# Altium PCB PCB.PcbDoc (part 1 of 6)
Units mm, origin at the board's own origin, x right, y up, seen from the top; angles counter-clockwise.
Board outline 101.6 x 101.61 mm, 4 copper layers (Top Layer, GND, POWER, Bottom Layer), stack 1.371 mm thick; 506 components, 346 nets, 1798 pads, 1471 vias.
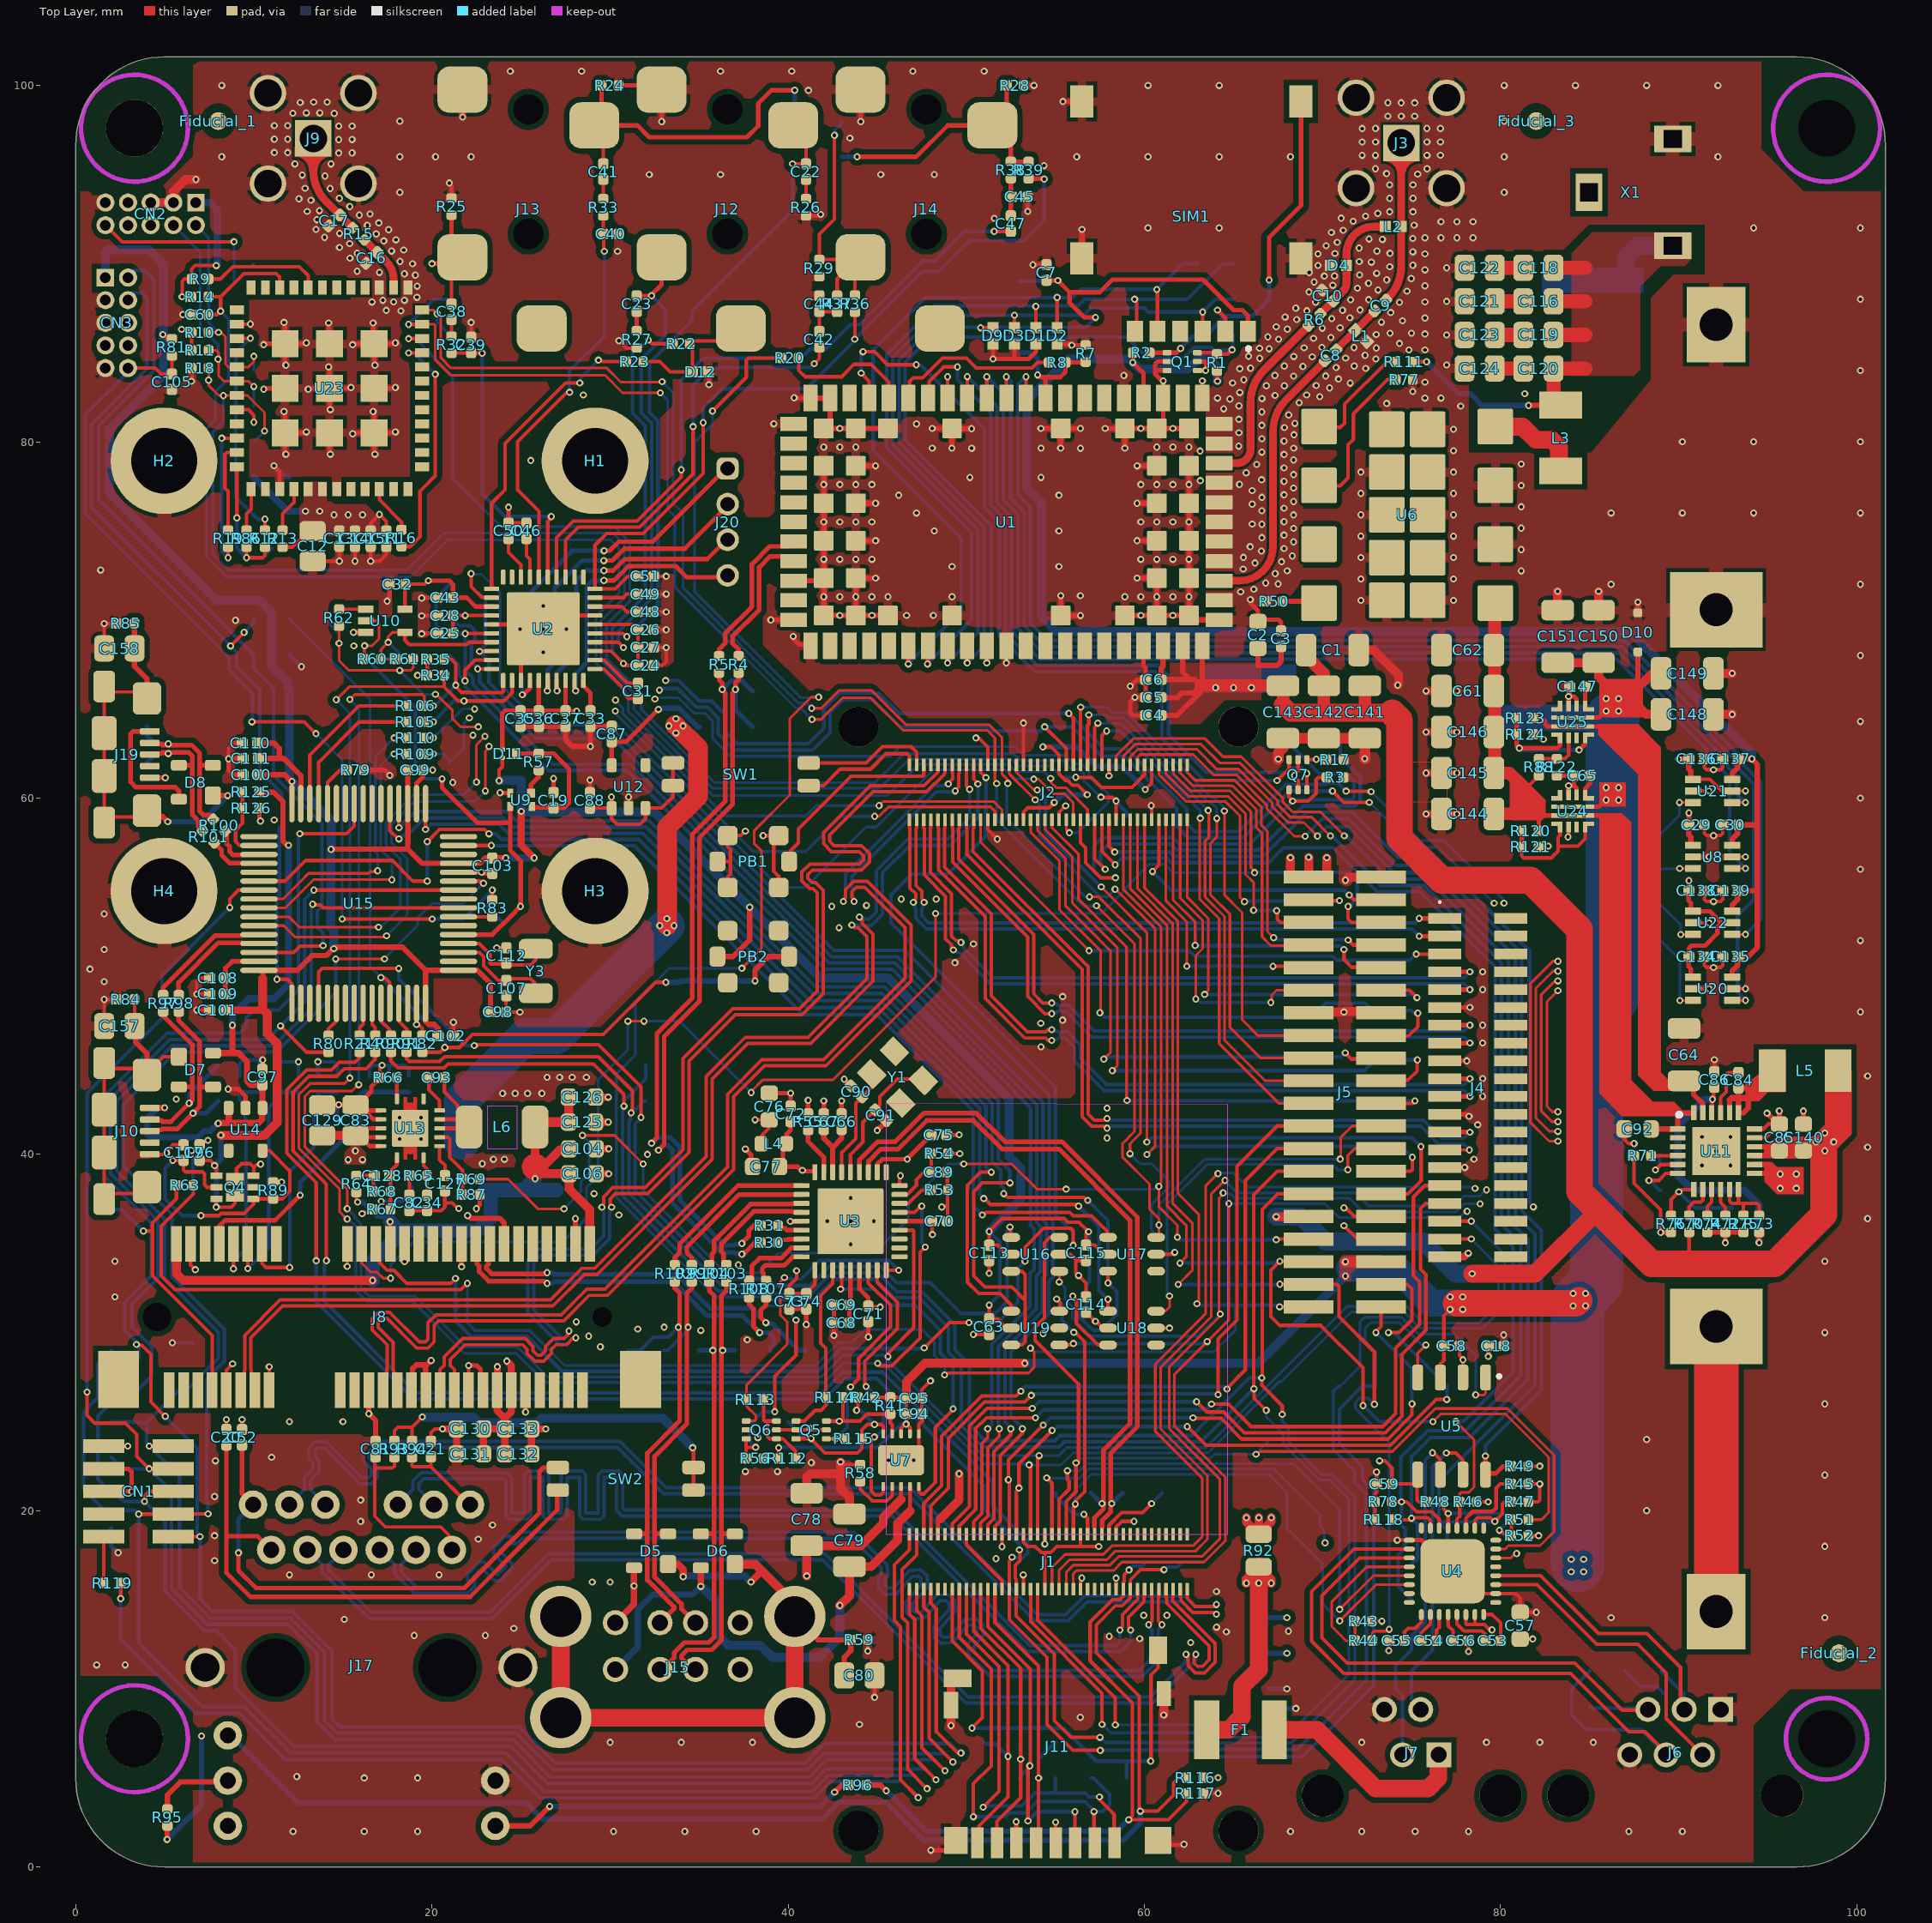
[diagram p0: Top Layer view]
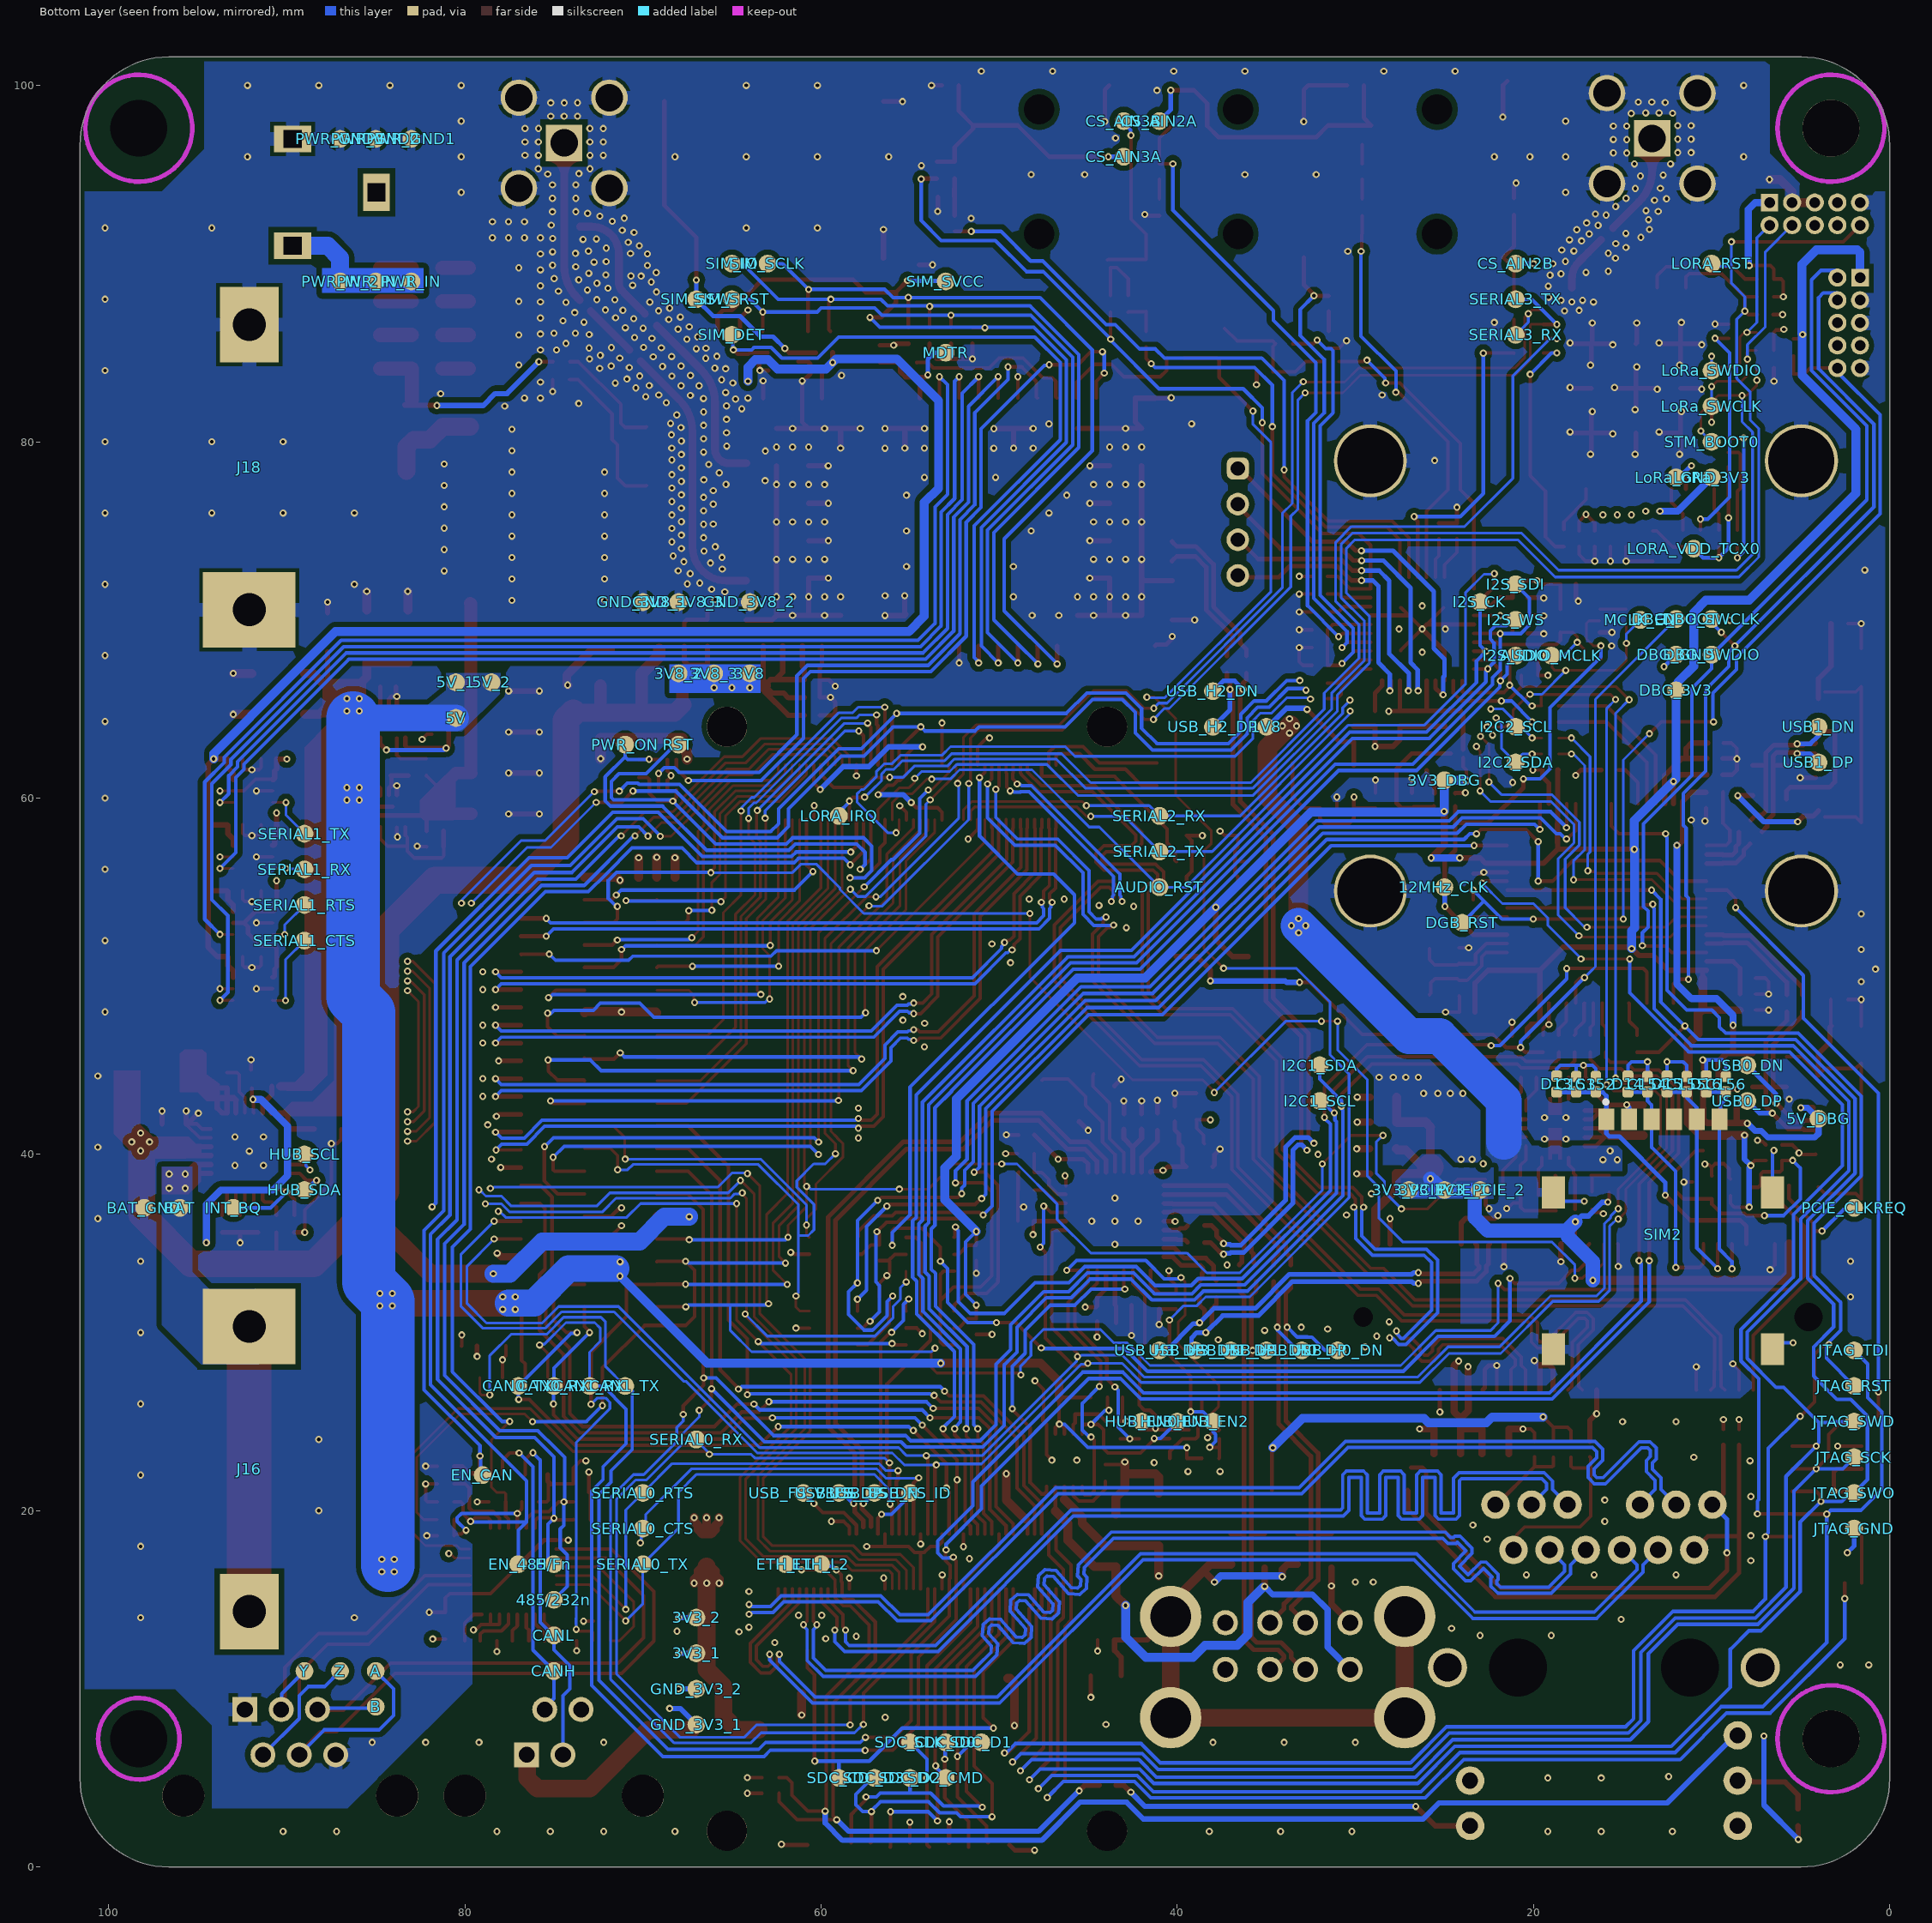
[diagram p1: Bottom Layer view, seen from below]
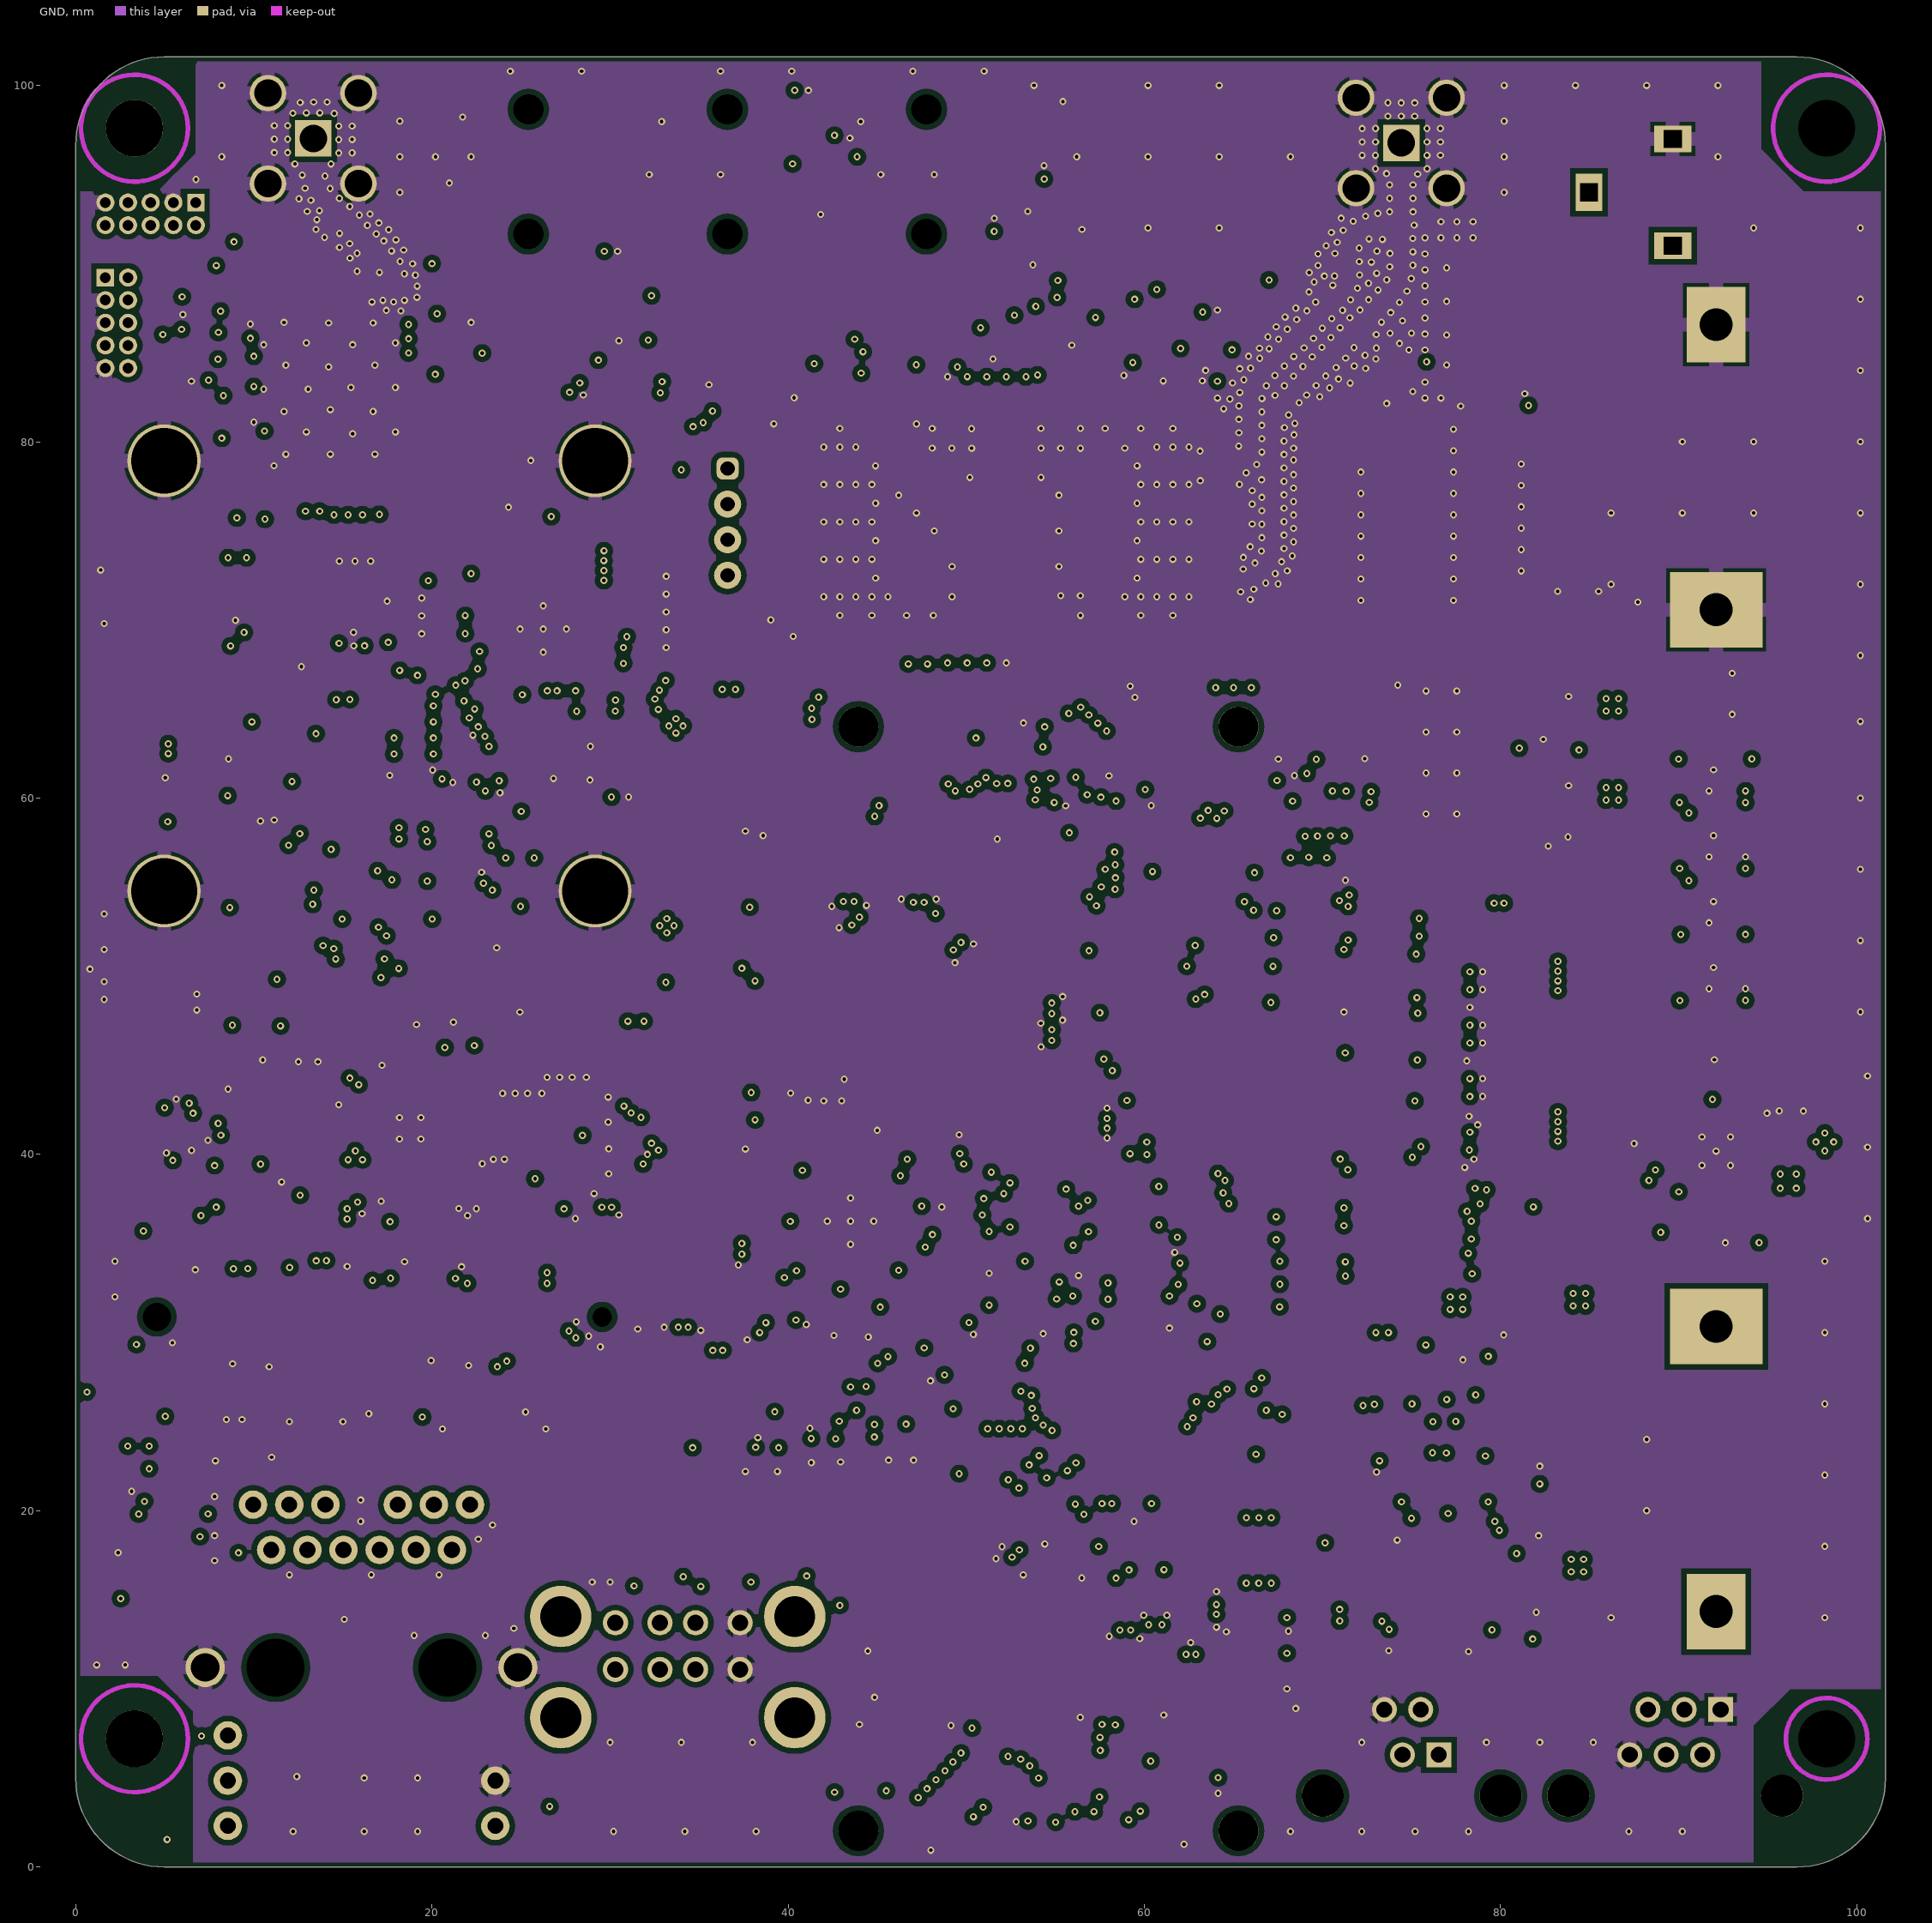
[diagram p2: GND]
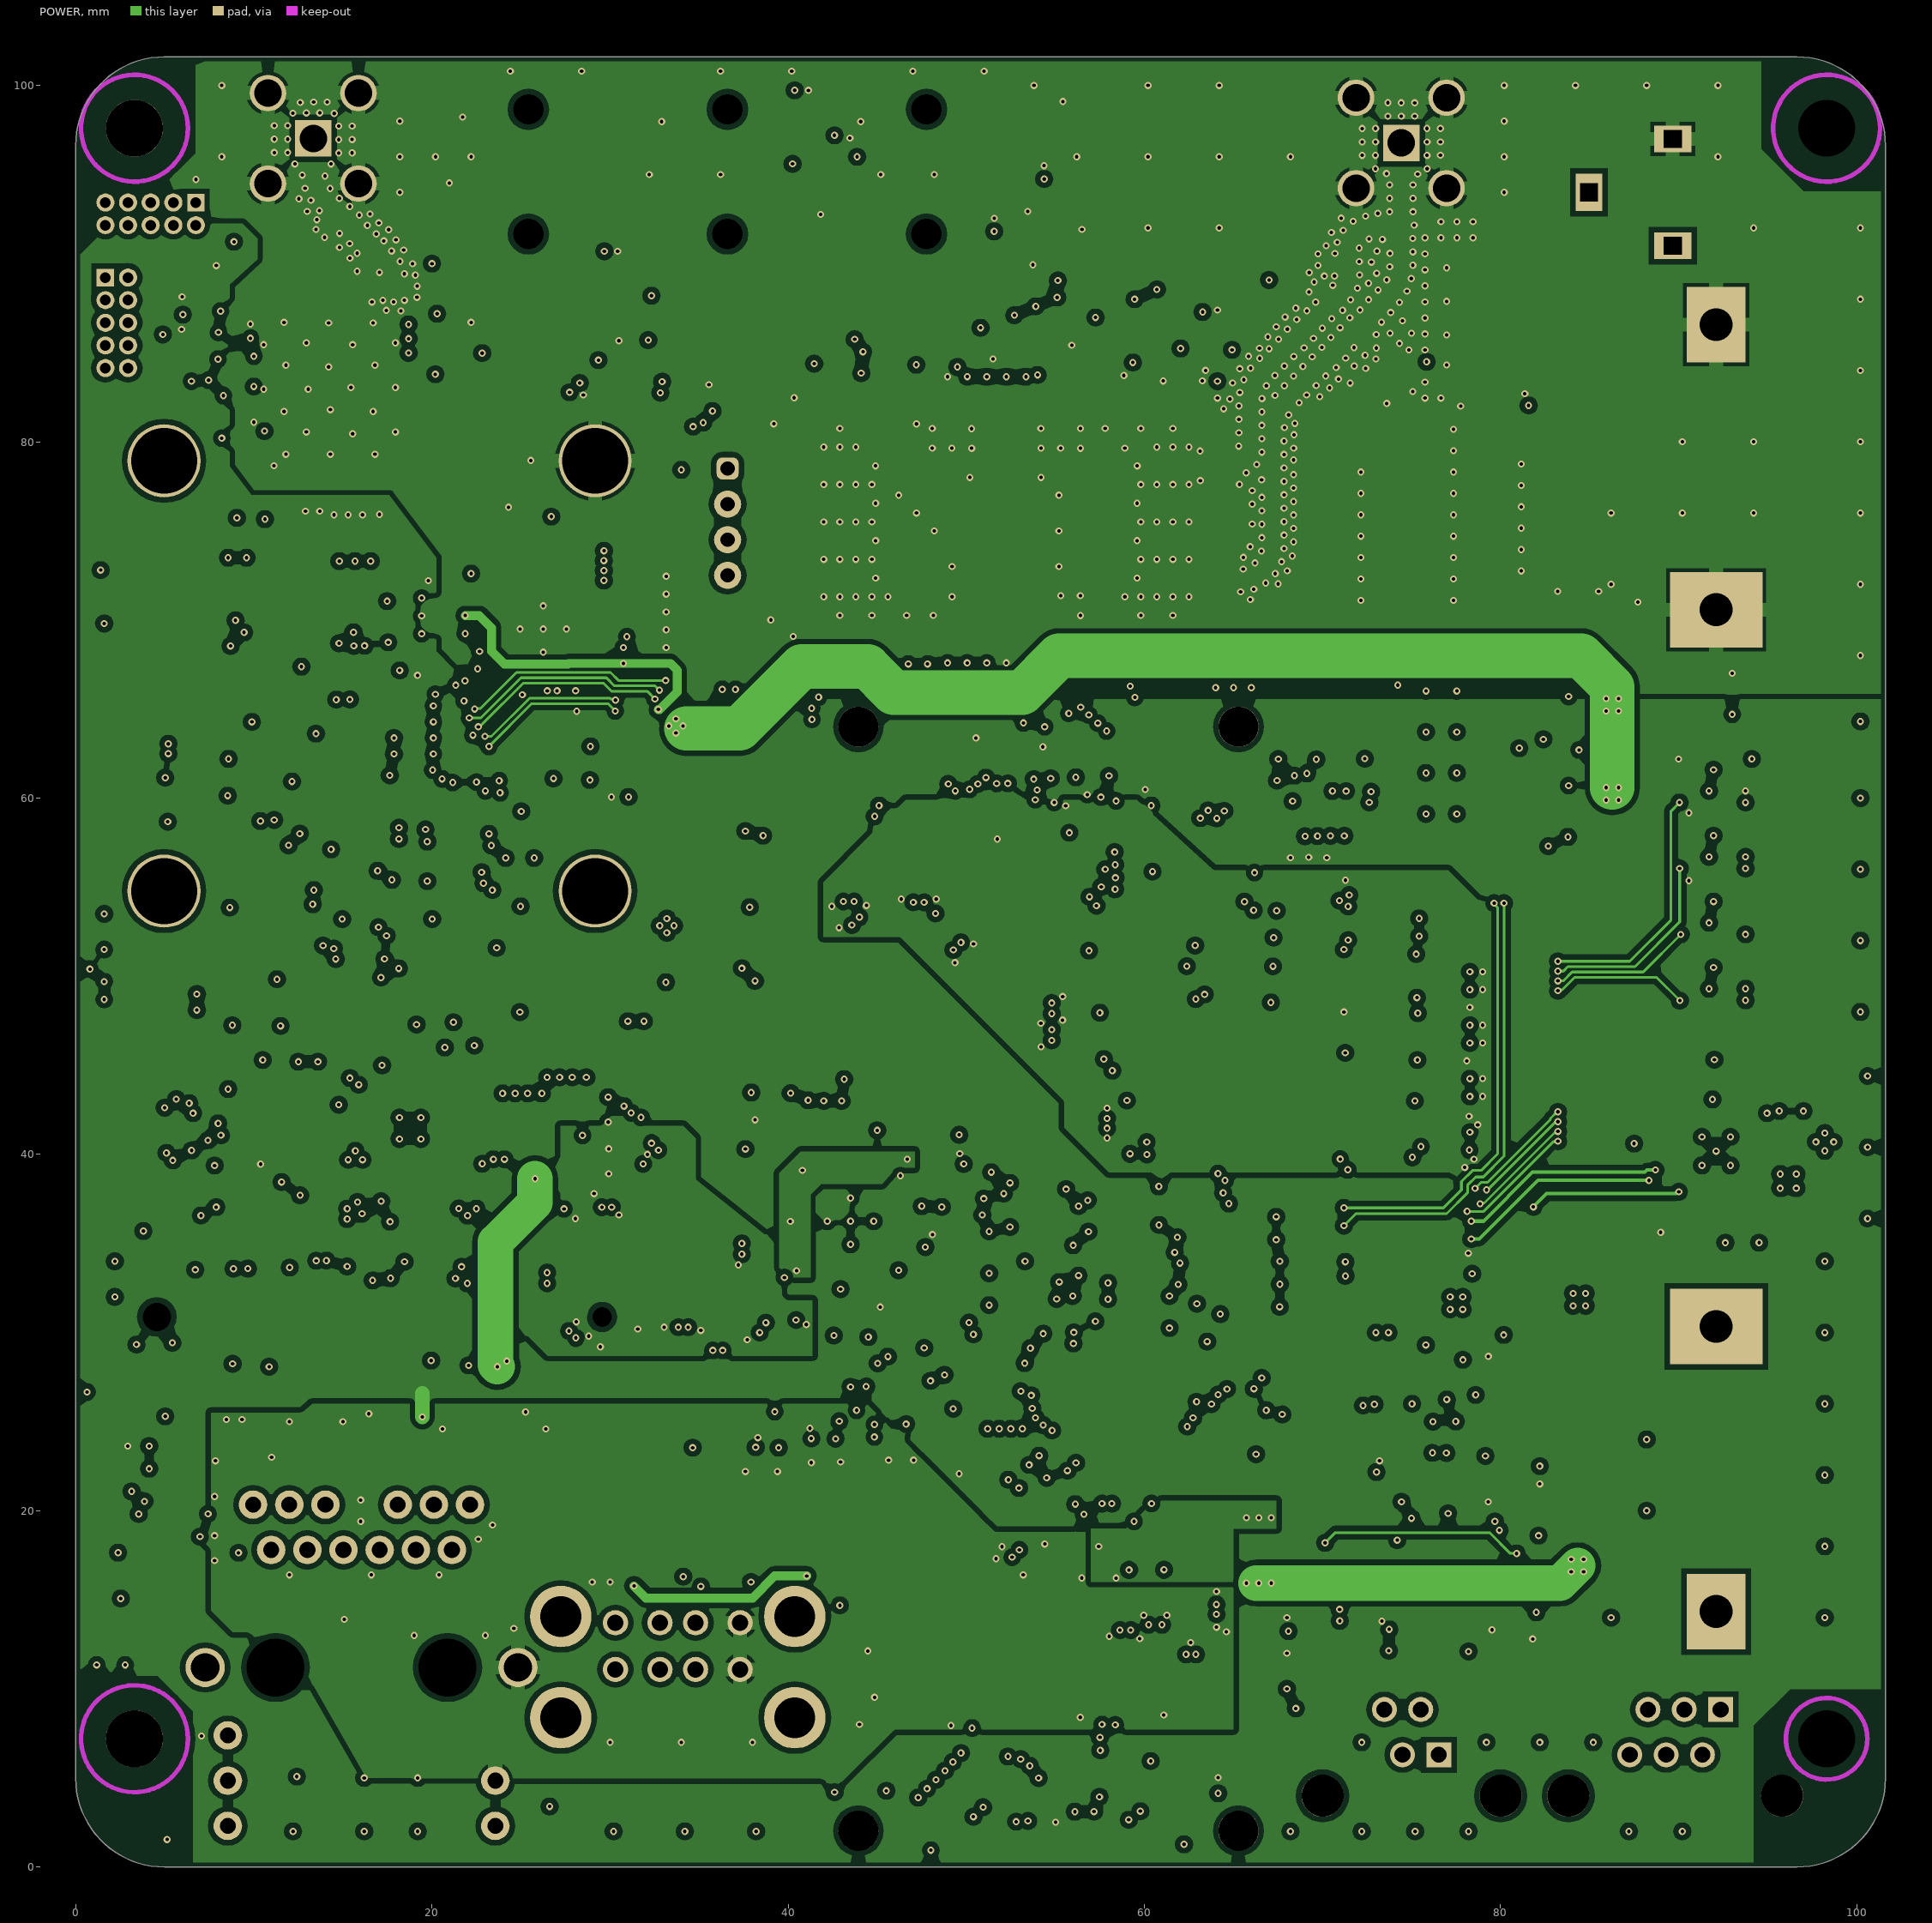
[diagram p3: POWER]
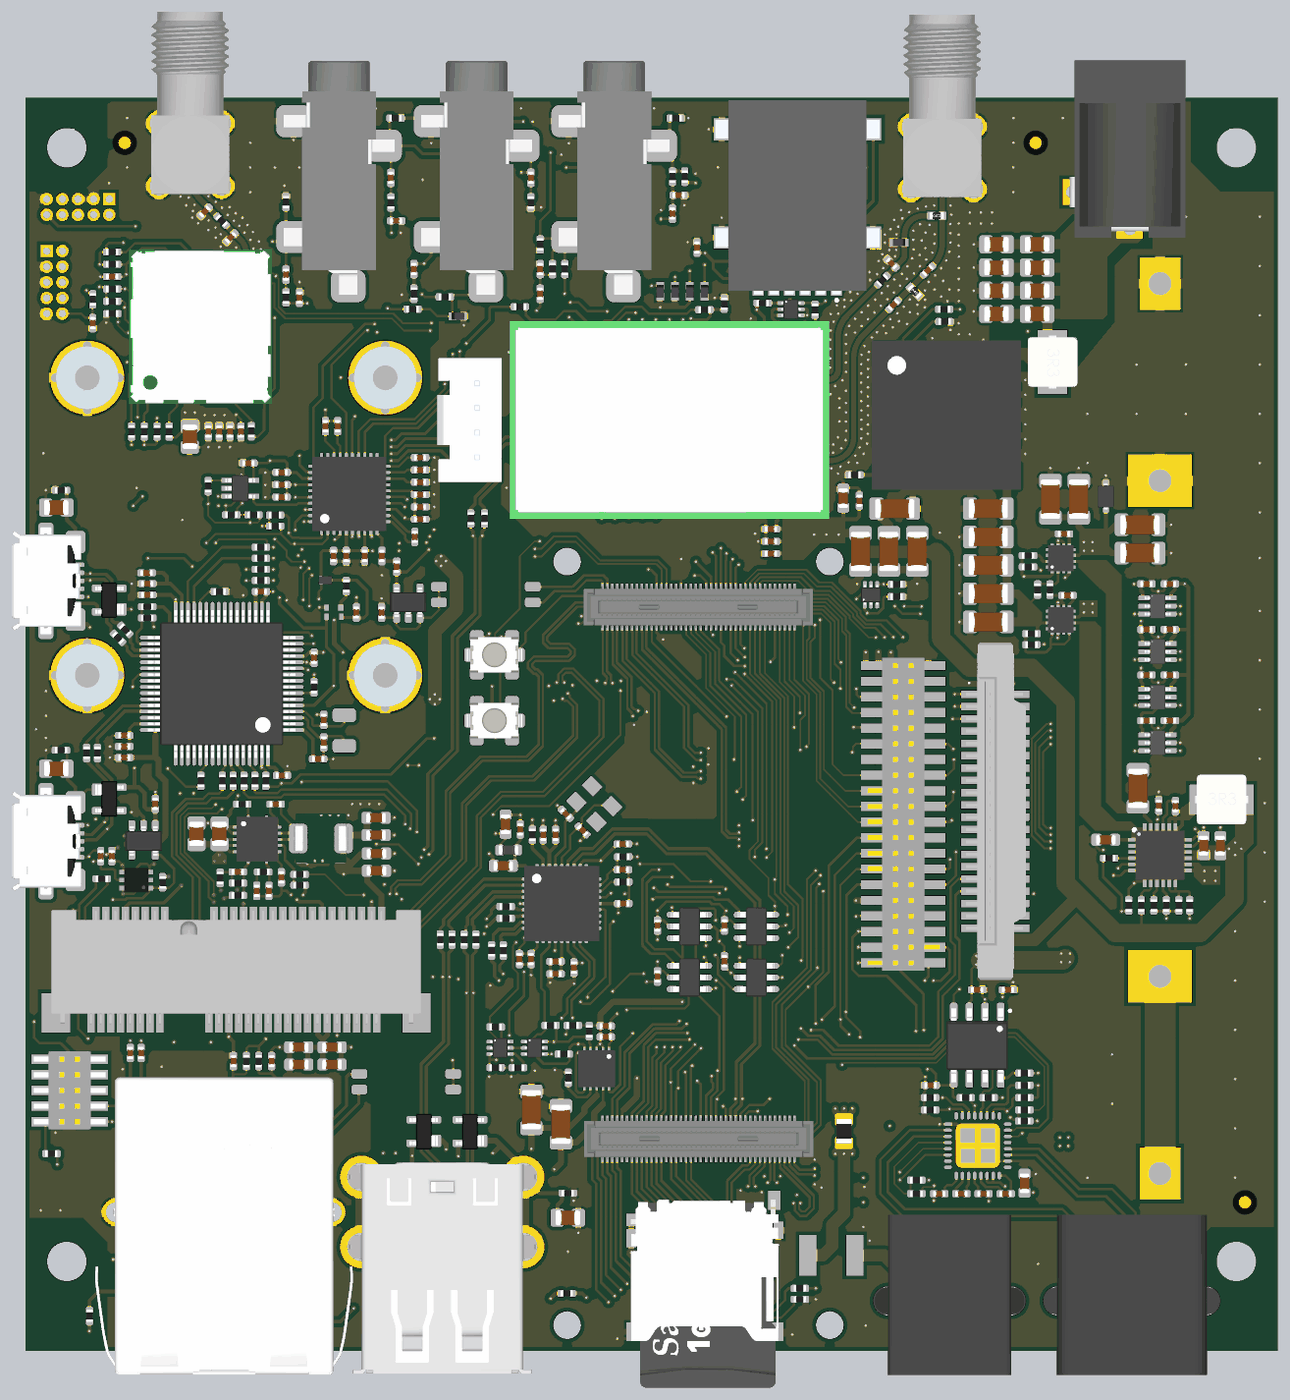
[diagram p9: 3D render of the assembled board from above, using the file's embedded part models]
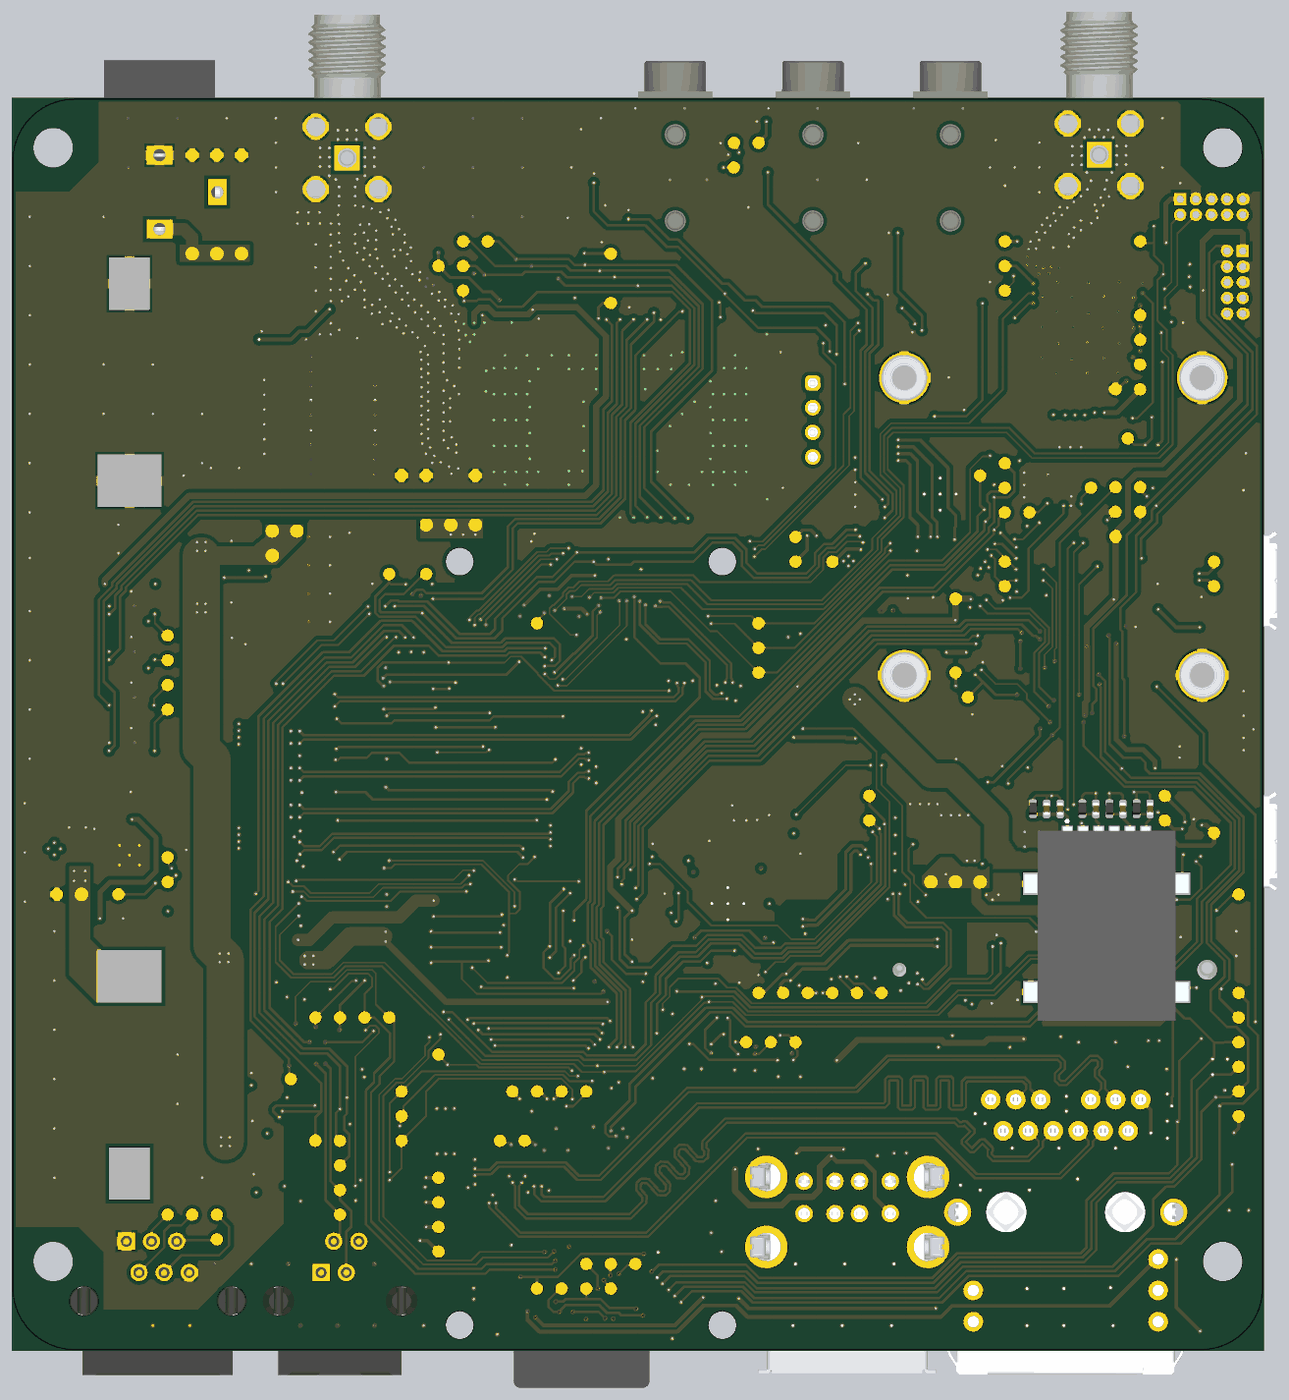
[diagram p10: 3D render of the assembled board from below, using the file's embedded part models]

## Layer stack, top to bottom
Top Solder: solder mask 0.025, SM-001, Dk 4
Top Layer: signal copper 0.035
Dielectric 1: prepreg 0.13, PP-017, Dk 4.3
Dielectric 2: prepreg 0.13, PP-017, Dk 4.3
GND: signal copper 0.035
Dielectric 3: core 0.711, Core-039, Dk 4.8
POWER: signal copper 0.035
Dielectric 4: prepreg 0.13, PP-017, Dk 4.3
Dielectric 5: prepreg 0.13, PP-017, Dk 4.3
Bottom Layer: signal copper 0.035
Bottom Solder: solder mask 0.025, SM-001, Dk 4

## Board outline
0,4.978 0.001,4.979 0.001,96.628 cw(c4.978,96.628) 4.978,101.606 4.978,101.605 96.627,101.605 cw(c96.627,96.627) 101.605,96.627 101.605,4.978 cw(c96.627,4.978) 96.627,0.001 4.978,0.001 cw(c4.978,4.978)

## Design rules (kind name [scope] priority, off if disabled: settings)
BoardOutlineClearance mousebits [(ObjectKind = 'Pad') And (Component = 'Free') And (Name = 'Free-T2') And (AsMM(HoleDiameter) = 0.5)] p1: gap=0 ignorepadtopadclearanceinfootprint=FALSE
BoardOutlineClearance [All] p2: gap=0.25 ignorepadtopadclearanceinfootprint=FALSE
Clearance RF_COPLANAR [InNamedPolygon('RF_COPLANAR')] p1: gap=0.15 ignorepadtopadclearanceinfootprint=FALSE
Clearance PWR3_3V3 [InNamedPolygon('+3V3A_L03_P069')] p2: gap=0.3 ignorepadtopadclearanceinfootprint=TRUE
Clearance Clearance_PWR [InPolygon] p3: gap=0.3 ignorepadtopadclearanceinfootprint=TRUE
Clearance Clearance_lay2 [All vs OnLayer('Layer 2')] p4: gap=0.3 ignorepadtopadclearanceinfootprint=TRUE
Clearance Clearance_gnd [InNet('GND')] p5: gap=0.15 ignorepadtopadclearanceinfootprint=TRUE
Clearance [All] p6: gap=0.15 ignorepadtopadclearanceinfootprint=TRUE
ComponentClearance TP_to_TP [HasFootprint('TP-1.00MM') vs HasFootprint('TP-1.00MM')] p1: gap=0.85 collisioncheckmode=3 verticalgap=-10 showdistances=FALSE
ComponentClearance BATTERY [All vs (ObjectKind = 'Component') And (Comment = '254TR')] p2: gap=-100 collisioncheckmode=3 verticalgap=2540 showdistances=FALSE
ComponentClearance STANDOFF [All vs (ObjectKind = 'Component') And (Footprint = 'STM-LQFP64_M')] p3: gap=0 collisioncheckmode=3 verticalgap=2540 showdistances=FALSE
ComponentClearance [All] p4: gap=0.254 collisioncheckmode=3 verticalgap=0.254 showdistances=FALSE
DiffPairsRouting [InDifferentialPairClass('PCIE')] p1: maxlimit=0.254 minlimit=0.15 mostfreqgap=0.254 toplayer_maxgap=0.15 toplayer_prefgap=0.15 toplayer_minwidth=0.26 toplayer_maxwidth=0.26 toplayer_prefwidth=0.26 bottomlayer_maxgap=0.15 bottomlayer_prefgap=0.15 bottomlayer_minwidth=0.26 bottomlayer_maxwidth=0.26 bottomlayer_prefwidth=0.26 impedanceprofiledriven=TRUE impedanceprofileid={86AA89F2-88DE-4668-8F6C-DF2D7110B5BD} impedanceprofilevalue=90.000000 maxuncoupledlength=12.7
DiffPairsRouting DiffPairsRouting_USB [InDifferentialPairClass('USB')] p2: maxlimit=0.254 minlimit=0.15 mostfreqgap=0.254 toplayer_maxgap=0.15 toplayer_prefgap=0.15 toplayer_minwidth=0.26 toplayer_maxwidth=0.26 toplayer_prefwidth=0.26 bottomlayer_maxgap=0.15 bottomlayer_prefgap=0.15 bottomlayer_minwidth=0.26 bottomlayer_maxwidth=0.26 bottomlayer_prefwidth=0.26 impedanceprofiledriven=TRUE impedanceprofileid={86AA89F2-88DE-4668-8F6C-DF2D7110B5BD} impedanceprofilevalue=90.000000 maxuncoupledlength=12.7
DiffPairsRouting DiffPairsRouting_ETH [InDifferentialPairClass('ETH')] p3: maxlimit=0.254 minlimit=0.15 mostfreqgap=0.254 toplayer_maxgap=0.15 toplayer_prefgap=0.15 toplayer_minwidth=0.19 toplayer_maxwidth=0.19 toplayer_prefwidth=0.19 bottomlayer_maxgap=0.15 bottomlayer_prefgap=0.15 bottomlayer_minwidth=0.19 bottomlayer_maxwidth=0.19 bottomlayer_prefwidth=0.19 impedanceprofiledriven=TRUE impedanceprofileid={794067FB-18C5-4D87-800B-9EEDAD137A72} impedanceprofilevalue=100.000000 maxuncoupledlength=12.7
DiffPairsRouting DiffPairsRouting_DSI [InDifferentialPairClass('DSI')] p4: maxlimit=0.254 minlimit=0.15 mostfreqgap=0.254 toplayer_maxgap=0.15 toplayer_prefgap=0.15 toplayer_minwidth=0.19 toplayer_maxwidth=0.19 toplayer_prefwidth=0.19 bottomlayer_maxgap=0.15 bottomlayer_prefgap=0.15 bottomlayer_minwidth=0.19 bottomlayer_maxwidth=0.19 bottomlayer_prefwidth=0.19 impedanceprofiledriven=TRUE impedanceprofileid={794067FB-18C5-4D87-800B-9EEDAD137A72} impedanceprofilevalue=100.000000 maxuncoupledlength=12.7
DiffPairsRouting DiffPairsRouting_CAMERA [InDifferentialPairClass('CAMERA')] p5: maxlimit=0.254 minlimit=0.15 mostfreqgap=0.254 toplayer_maxgap=0.15 toplayer_prefgap=0.15 toplayer_minwidth=0.19 toplayer_maxwidth=0.19 toplayer_prefwidth=0.19 bottomlayer_maxgap=0.15 bottomlayer_prefgap=0.15 bottomlayer_minwidth=0.19 bottomlayer_maxwidth=0.19 bottomlayer_prefwidth=0.19 impedanceprofiledriven=TRUE impedanceprofileid={794067FB-18C5-4D87-800B-9EEDAD137A72} impedanceprofilevalue=100.000000 maxuncoupledlength=12.7
HoleSize [All] p1 off: absolutevalues=TRUE maxlimit=2.54 minlimit=0.025 maxpercent=80.000 minpercent=20.000
MatchedLengths match_PCIE [InDifferentialPairClass('PCIE')] p1: tolerance=1.5 checknetsindiffpair=TRUE checkdiffpairvsdiffpair=FALSE checkxsignals=FALSE checkothers=FALSE
MatchedLengths MatchedLengths_eth [InDifferentialPairClass('ETH')] p2: tolerance=1.5 checknetsindiffpair=TRUE checkdiffpairvsdiffpair=FALSE checkxsignals=FALSE checkothers=FALSE
MatchedLengths MatchedLengths_dsi [InDifferentialPairClass('DSI')] p3: tolerance=1.5 checknetsindiffpair=TRUE checkdiffpairvsdiffpair=FALSE checkxsignals=FALSE checkothers=FALSE
MatchedLengths [InAnyDifferentialPair] p4: tolerance=1.5 checknetsindiffpair=TRUE checkdiffpairvsdiffpair=FALSE checkxsignals=FALSE checkothers=FALSE
PlaneConnect [All] p1: pad.planeconnectstyle=Relief pad.reliefexpansion=0.3 pad.reliefentries=4 pad.reliefconductorwidth=0.5 pad.reliefairgap=0.2 via.planeconnectstyle=Direct via.reliefexpansion=0.508 via.reliefentries=4 via.reliefconductorwidth=0.254 via.reliefairgap=0.254
PolygonConnect PWR_IN [All vs InNamedPolygon('PRW_IN')] p1: thpad.connectstyle=Direct thpad.reliefconductorwidth=0.254 thpad.reliefentries=4 thpad.polygonreliefangle="90 Angle" thpad.airgapwidth=0.254 smdpad.connectstyle=Relief smdpad.reliefconductorwidth=0.4 smdpad.reliefentries=4 smdpad.polygonreliefangle="90 Angle" smdpad.airgapwidth=0.4 via.connectstyle=Direct via.reliefconductorwidth=0.254 via.reliefentries=4 via.polygonreliefangle="90 Angle" via.airgapwidth=0.254
PolygonConnect No_reliefs [IsNamedPolygon('No_reliefs')] p2: connectstyle=Direct reliefconductorwidth=0.254 reliefentries=4 polygonreliefangle="90 Angle" airgapwidth=0.254
PolygonConnect RF_COPLANAR_1 [All vs IsNamedPolygon('RF_COPLANAR')] p3: thpad.connectstyle=Relief thpad.reliefconductorwidth=0.254 thpad.reliefentries=4 thpad.polygonreliefangle="90 Angle" thpad.airgapwidth=0.254 smdpad.connectstyle=Direct smdpad.reliefconductorwidth=0.254 smdpad.reliefentries=4 smdpad.polygonreliefangle="90 Angle" smdpad.airgapwidth=0.254 via.connectstyle=Direct via.reliefconductorwidth=0.254 via.reliefentries=4 via.polygonreliefangle="90 Angle" via.airgapwidth=0.254
PolygonConnect GND_only [InNet('GND')] p4: thpad.connectstyle=Relief thpad.reliefconductorwidth=0.8 thpad.reliefentries=4 thpad.polygonreliefangle="90 Angle" thpad.airgapwidth=0.2 smdpad.connectstyle=Relief smdpad.reliefconductorwidth=0.5 smdpad.reliefentries=4 smdpad.polygonreliefangle="90 Angle" smdpad.airgapwidth=0.2 via.connectstyle=Direct via.reliefconductorwidth=0.254 via.reliefentries=4 via.polygonreliefangle="90 Angle" via.airgapwidth=0.254
PolygonConnect Signal_only [All] p5: connectstyle=Direct reliefconductorwidth=0.254 reliefentries=4 polygonreliefangle="90 Angle" airgapwidth=0.254
RoomDefinition PORTENTA [InComponentClass('PORTENTA')] p1: confinementstyle=ConfineIn formatcopy=TRUE lockcomponents=FALSE outline 0,0 50.8,0 50.8,25.4 0,25.4
RoomDefinition ETH_CONNECTOR [InComponentClass('ETH_CONNECTOR')] p2: confinementstyle=ConfineIn formatcopy=TRUE lockcomponents=FALSE outline 0,0 50.8,0 50.8,25.4 0,25.4
RoomDefinition DBG [InComponentClass('DBG')] p3 off: confinementstyle=ConfineIn formatcopy=TRUE lockcomponents=FALSE outline 102.743,1.397 330.937,1.397 330.937,18.567 102.743,18.567
RoomDefinition "USB Host" [InComponentClass('USB Host')] p4 off: confinementstyle=ConfineIn formatcopy=TRUE lockcomponents=FALSE outline 0,0 50.8,0 50.8,25.4 0,25.4
RoomDefinition TOP [InComponentClass('TOP')] p5 off: confinementstyle=ConfineIn formatcopy=TRUE lockcomponents=FALSE outline 0,0 50.8,0 50.8,25.4 0,25.4
RoomDefinition SD [InComponentClass('SD')] p6 off: confinementstyle=ConfineIn formatcopy=TRUE lockcomponents=FALSE outline 102.743,5.055 107.086,5.055 107.086,9.728 102.743,9.728
RoomDefinition "RS485 and CAN" [InComponentClass('RS485 and CAN')] p7 off: confinementstyle=ConfineIn formatcopy=TRUE lockcomponents=FALSE outline 0,0 50.8,0 50.8,25.4 0,25.4
RoomDefinition "Power supply" [InComponentClass('Power supply')] p8 off: confinementstyle=ConfineIn formatcopy=TRUE lockcomponents=FALSE outline 0,0 50.8,0 50.8,25.4 0,25.4
RoomDefinition PCIE [InComponentClass('PCIE')] p9 off: confinementstyle=ConfineIn formatcopy=TRUE lockcomponents=FALSE outline 0,0 50.8,0 50.8,25.4 0,25.4
RoomDefinition "Lora Module" [InComponentClass('Lora Module')] p10 off: confinementstyle=ConfineIn formatcopy=TRUE lockcomponents=FALSE outline 0,0 50.8,0 50.8,25.4 0,25.4
RoomDefinition HUB [InComponentClass('HUB')] p11 off: confinementstyle=ConfineIn formatcopy=TRUE lockcomponents=FALSE outline 0,0 50.8,0 50.8,25.4 0,25.4
RoomDefinition "Cellular Module" [InComponentClass('Cellular Module')] p12 off: confinementstyle=ConfineIn formatcopy=TRUE lockcomponents=FALSE outline 102.743,1.397 106.07,1.397 106.07,5.156 102.743,5.156
RoomDefinition Camera [InComponentClass('Camera')] p13 off: confinementstyle=ConfineIn formatcopy=TRUE lockcomponents=FALSE outline 0,0 50.8,0 50.8,25.4 0,25.4
RoomDefinition Audio [InComponentClass('Audio')] p14 off: confinementstyle=ConfineIn formatcopy=TRUE lockcomponents=FALSE outline 0,0 50.8,0 50.8,25.4 0,25.4
RoutingVias [All] p1: holewidth=0.2 width=0.4 viastyle="Through Hole" minholewidth=0.2 minwidth=0.4 maxholewidth=0.2 maxwidth=0.4
SolderMaskExpansion [IsVia] p1: expansion=0.102 istentingtop=TRUE
SolderMaskExpansion SolderMaskExpansion_1 [All] p2: expansion=0.05 istentingtop=FALSE
ViasUnderSMD [All] p1: allowed=FALSE
Width 50R [InNet('NetC17_2') OR InNet('NetC16_2')  OR InNet('NetC8_1') OR InNet('NetR6_1')] p1: maxlimit=0.447 minlimit=0.274 preferedwidth=0.447 toplayer_minwidth=0.44 midlayer1_maxwidth=0.284 midlayer1_prefwidth=0.284 midlayer2_maxwidth=0.284 midlayer2_prefwidth=0.284 bottomlayer_minwidth=0.44 impedanceprofiledriven=TRUE impedanceprofileid={5C83D50C-043A-4C5B-A4AB-3CBF0BAC11ED} impedanceprofilevalue=50.000000 minimp=50.000000 maximp=50.000000 favimp=50.000000
Width [All] p2: maxlimit=5 minlimit=0.15 preferedwidth=0.2
26 further rules are at their usual default settings.

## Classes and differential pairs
differential pair class CAMERA: CAMERA.CK_1 CAMERA.D0_1 CAMERA.D1_1 CAMERA.D2_1 CAMERA.D3_1
differential pair class DSI: CAMERA.CK_CK_1 CAMERA.D0_D0_1 CAMERA.D1_D0_1 CAMERA.D2_D1_1 CAMERA.D3_D1_1 CAMERA.D4_D2_1 CAMERA.D5_D2_1 CAMERA.D6_D3_1 CAMERA.VS_CK_1 PCIe.CK_1 PCIe.RX_1 PCIe.TX_1
differential pair class PCIE: PCIe.CK_1 PCIe.RX_1 PCIe.TX_1
differential pair class ETH: ETH.A_1 ETH.B_1 ETH.C_1 ETH.D_1
component class DBG: C63 C98 C99 C100 C101 C102 C103 C105 C107 C108 C109 C110 C111 C112 C113 C114 C115 C157 C158 CN3 D7 D8 DBG_3V3 DBG_BOOT DBG_GND DBG_SWCLK DBG_SWDIO DGB_RST J10 J19 PB2 R21 R40 R79 R80 R81 R82 R83 R84 R85 R90 R91 R97 R98 R100 R101 R105 R106 R109 R110 R125 R126 U15 U16 U17 U18 U19 USB0_DN USB0_DP USB1_DN USB1_DP Y3
polygon class GND-BOT: +3V8_L01_P032
differential pair class USB: U0_D U1_D USB0_8 USB0_D_3 USB0_D_RES_3 USB1_8 USB1_D_3 USB1_D_uC_3 USB2_8 USB3_8 USB_FS.D_1 USB_H0.D_1 USB_H1.D_1 USB_H2.D_1 USB_H3.D_1 USB_R_5
component class TOP: 3V3_1 3V3_2 12MHz_CLK AUDIO_MCLK C19 C32 CAN0_RX CAN0_TX CAN1_RX CAN1_TX D11 Fiducial_1 Fiducial_2 Fiducial_3 GND_3V3_1 GND_3V3_2 HUB_SCL HUB_SDA I2C1_SCL I2C1_SDA I2C2_SCL I2C2_SDA I2S_CK I2S_SDI I2S_SDO I2S_WS J5 JTAG_GND JTAG_RST JTAG_SCK JTAG_SWD JTAG_SWO JTAG_TDI MCLK_EN PB1 R57 R60 R61 R62 R92 SERIAL0_CTS SERIAL0_RTS SERIAL0_RX SERIAL0_TX SERIAL1_CTS SERIAL1_RTS SERIAL1_RX SERIAL1_TX SERIAL2_RX SERIAL2_TX SERIAL3_RX SERIAL3_TX SW1 U9 U10 USB_FS_DN USB_FS_DP USB_FS_ID USB_FS_VBUS USB_H0_DN USB_H0_DP USB_H1_DN USB_H1_DP USB_H2_DN USB_H2_DP USB_H3_DN USB_H3_DP
component class "USB Host": C78 C79 C80 C94 C95 D5 D6 J15 R58 R59 U7
component class SD: J11 SDC_CD SDC_CLK SDC_CMD SDC_D0 SDC_D1 SDC_D2 SDC_D3
component class "RS485 and CAN": 485/232n A B C53 C54 C55 C56 C57 C58 C59 CANH CANL EN_485 EN_CAN F1 H/Fn J6 J7 R43 R44 R45 R46 R47 R48 R49 R51 R52 R78 R118 U4 U5 Y Z
component class "Power supply": 1V8 3V3_DBG 3V3_PCIE 3V3_PCIE_1 3V3_PCIE_2 3V8 3V8_2 3V8_3 5V 5V_1 5V_2 5V_DBG BAT BAT_GND C34 C61 C62 C64 C65 C82 C83 C84 C85 C86 C87 C88 C92 C93 C96 C97 C104 C106 C116 C117 C118 C119 C120 C121 C122 C123 C124 C125 C126 C127 C128 C129 C140 C144 C145 C146 C147 C148 C149 C150 C151 D10 GND_3V8_1 GND_3V8_2 GND_3V8_3 INT_BQ J16 J18 L3 L5 L6 PWR_GND1 PWR_GND2 PWR_GND3 PWR_IN PWR_IN_1 PWR_IN_2 Q4 R50 R64 R65 R66 R67 R68 R69 R70 R71 R72 R73 R74 R75 R76 R77 R87 R88 R89 R111 R120 R121 R122 R123 R124 U6 U11 U12 U13 U14 U24 U25 X1
component class PCIE: C130 C131 C132 C133 C152 C153 C154 C155 C156 D13 D14 D15 D16 H1 H2 H3 H4 J8 PCIE_CLKREQ R63 SIM2
component class HUB: C66 C67 C68 C69 C70 C71 C72 C73 C74 C75 C76 C77 C89 C90 C91 HUB_EN0 HUB_EN1 HUB_EN2 L4 Q5 Q6 R30 R31 R41 R42 R53 R54 R55 R56 R99 R102 R103 R104 R107 R108 R112 R113 R114 R115 U3 Y1
component class ETH_CONNECTOR: C20 C21 C52 C81 ETH_L1 ETH_L2 J17 R93 R94 R95 R96 R116 R117 SW2
component class "Cellular Module": C1 C2 C3 C4 C5 C6 C7 C8 C9 C10 C29 C30 C134 C135 C136 C137 C138 C139 C141 C142 C143 D1 D2 D3 D4 D9 J3 L1 L2 MDTR PWR_ON Q1 Q7 R1 R2 R3 R4 R5 R6 R7 R8 R17 R20 RST SIM1 SIM_DET SIM_IO SIM_SCLK SIM_SRST SIM_SSW SIM_SVCC U1 U8 U20 U21 U22
component class Camera: C18 J4
component class Audio: AUDIO_RST C22 C23 C24 C25 C26 C27 C28 C31 C33 C35 C36 C37 C38 C39 C40 C41 C42 C43 C44 C45 C46 C47 C48 C49 C50 C51 CS_AIN2A CS_AIN2B CS_AIN3A CS_AIN3B D12 J12 J13 J14 J20 R22 R23 R24 R25 R26 R27 R28 R29 R32 R33 R34 R35 R36 R37 R38 R39 U2
component class "Lora Module": C11 C12 C13 C14 C15 C16 C17 C60 CN2 J9 LoRa_3V3 LoRa_GND LORA_IRQ LORA_RST LoRa_SWCLK LoRa_SWDIO LORA_VDD_TCX0 R9 R10 R11 R12 R13 R14 R15 R16 R18 R19 R86 STM_BOOT0 U23
component class PORTENTA: CN1 J1 J2 R119
differential pair USB0_D_RES_3: +USB0_D_RES_3_P -USB0_D_RES_3_N
differential pair USB0_D_3: +USB0_D_3_P -USB0_D_3_N
differential pair USB2_8: +USB2_8_P -USB2_8_N
differential pair USB_R_5: +USB_R_5_P -USB_R_5_N
differential pair USB3_8: +USB3_8_P -USB3_8_N
differential pair USB1_D_uC_3: +USB1_D_uC_3_P -USB1_D_uC_3_N
differential pair USB1_D_3: +USB1_D_3_P -USB1_D_3_N
differential pair USB1_8: +USB1_8_P -USB1_8_N
differential pair USB0_8: +USB0_8_P -USB0_8_N
differential pair CAMERA.D3_1: +CAMERA.D3_1_P -CAMERA.D3_1_N
differential pair CAMERA.D2_1: +CAMERA.D2_1_P -CAMERA.D2_1_N
differential pair CAMERA.D1_1: +CAMERA.D1_1_P -CAMERA.D1_1_N
differential pair CAMERA.D0_1: +CAMERA.D0_1_P -CAMERA.D0_1_N
differential pair CAMERA.CK_1: +CAMERA.CK_1_P -CAMERA.CK_1_N
differential pair USB_H3.D_1: +USB_H3.D_1_P -USB_H3.D_1_N
differential pair USB_H2.D_1: +USB_H2.D_1_P -USB_H2.D_1_N
differential pair USB_H1.D_1: +USB_H1.D_1_P -USB_H1.D_1_N
differential pair USB_H0.D_1: +USB_H0.D_1_P -USB_H0.D_1_N
differential pair USB_FS.D_1: +USB_FS.D_1_P -USB_FS.D_1_N
differential pair PCIe.TX_1: +PCIe.TX_1_P -PCIe.TX_1_N
differential pair PCIe.RX_1: +PCIe.RX_1_P -PCIe.RX_1_N
differential pair PCIe.CK_1: +PCIe.CK_1_P -PCIe.CK_1_N
differential pair ETH.D_1: +ETH.D_1_P -ETH.D_1_N
differential pair ETH.C_1: +ETH.C_1_P -ETH.C_1_N
differential pair ETH.B_1: +ETH.B_1_P -ETH.B_1_N
differential pair ETH.A_1: +ETH.A_1_P -ETH.A_1_N

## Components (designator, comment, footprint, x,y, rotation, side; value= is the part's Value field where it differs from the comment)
1V8 "CMP-018-0005-A.3" TP-1.00MM#1 35,64 r90 bottom
3V3_1 "CMP-018-0005-A.3" TP-1.00MM#1 67,12 r180 bottom
3V3_2 "CMP-018-0005-A.3" TP-1.00MM#1 67,14 r180 bottom
3V3_DBG "CMP-018-0005-A.3" TP-1.00MM#1 25,61 r180 bottom
3V3_PCIE "CMP-018-0005-A.3" TP-1.00MM#1 27,38 r90 bottom
3V3_PCIE_1 "CMP-018-0005-A.3" TP-1.00MM#1 25,38 r90 bottom
3V3_PCIE_2 "CMP-018-0005-A.3" TP-1.00MM#1 23,38 r90 bottom
3V8 "CMP-018-0005-A.3" TP-1.00MM#1 64,67 r180 bottom
3V8_2 "CMP-018-0005-A.3" TP-1.00MM#1 68,67 r180 bottom
3V8_3 "CMP-018-0005-A.3" TP-1.00MM#1 66,67 r180 bottom
5V "CMP-018-0005-A.3" TP-1.00MM#1 80.5,64.5 r180 bottom
5V_1 "CMP-018-0005-A.3" TP-1.00MM#1 80.5,66.5 r90 bottom
5V_2 "CMP-018-0005-A.3" TP-1.00MM#1 78.5,66.5 r90 bottom
5V_DBG "CMP-018-0005-A.3" TP-1.00MM#1 4,42 r90 bottom
12MHz_CLK "CMP-018-0005-A.3" TP-1.00MM#1 25,55 r180 bottom
485/232n "CMP-018-0005-A.3" TP-1.00MM#1 75,15 r180 bottom
A "CMP-018-0005-A.3" TP-1.00MM#1 85,11 r270 bottom
AUDIO_MCLK "CMP-018-0005-A.3" TP-1.00MM#1 19,68 r180 bottom
AUDIO_RST "CMP-018-0005-A.3" TP-1.00MM#1 41,55 r180 bottom
B "CMP-018-0005-A.3" TP-1.00MM#1 85,9 r270 bottom
BAT "CMP-018-0005-A.3" TP-1.00MM#1 96,37 r0 bottom
BAT_GND "CMP-018-0005-A.3" TP-1.00MM#1 98,37 r0 bottom
C1 "CL31A107MPHNNNE" CAP-1206#1 70.55,68.31 r180 top value=100µF
C2 "GRM188R61E106MA73J" CAP-0603#1 66.375,69.16 r270 top value=10µF
C3 "C0402C104K4RACTU" CAP-0402#1 67.675,68.945 r270 top value=100nF
C4 "C0402C103K5RACTU" CAP-0402#1 60.5,64.65 r0 top value=10nF
C5 "04025A680JAT2A" CAP-0402#1 60.5,65.65 r0 top value=68pF
C6 "C0402C150J5GACTU" CAP-0402#1 60.5,66.65 r0 top value=15pF
C7 "C0402C104K4RACTU" CAP-0402#1 54.5,89.5 r90 top value=100nF
C8 "C0402C150J5GACTU" CAP-0402#1 70.45,84.85 r45 top value=15pF
C9 "GRM1555C1H330JA01D" CAP-0402#1 73.246,87.646 r45 top value=33pF
C10 "C0402C104K4RACTU" CAP-0402#1 70.292,88.208 r315 top value=100nF
C11 "C0402C105K8PACTU" CAP-0402#1 17.44,74.565 r90 top value=1µF
C12 "CL21A226MAQNNNE" CAP-0805#1 13.3,74.15 r90 top value=22µF
C13 "C0402C104K4RACTU" CAP-0402#1 14.8,74.565 r90 top value=100nF
C14 "C0402C104K4RACTU" CAP-0402#1 15.68,74.565 r90 top value=100nF
C15 "C0402C104K4RACTU" CAP-0402#1 16.56,74.565 r90 top value=100nF
C16 "C0402C104K4RACTU" CAP-0402#1 16.613,90.322 r45 top value=100nF
C17 "C0402C104K4RACTU" CAP-0402#1 14.514,92.421 r45 top value=100nF
C18 "C0402C104K4RACTU" CAP-0402#1 79.75,29.25 r180 top value=100nF
C19 "C0402C104K4RACTU" CAP-0402#1 26.825,59.875 r270 top value=100nF
C20 "C0402C104K4RACTU" CAP-0402#2 8.459,24.123 r90 top value=100nF
C21 "C0402C104K4RACTU" CAP-0402#1 19.941,23.465 r90 top value=100nF
C22 "CL05B223KP5NNNC" CAP-0402#1 41,95.162 r90 top value=22nF
C23 "CL05B223KP5NNNC" CAP-0402#1 31.5,87.75 r90 top value=22nF
C24 "C0402C105K8PACTU" CAP-0402#1 32,67.45 r180 top value=1µF
C25 "C0402C104K4RACTU" CAP-0402#1 20.75,69.25 r0 top value=100nF
C26 "C0402C104K4RACTU" CAP-0402#1 32,69.45 r180 top value=100nF
C27 "C0402C104K4RACTU" CAP-0402#1 32,68.45 r180 top value=100nF
C28 "C0402C105K8PACTU" CAP-0402#1 20.75,70.25 r0 top value=1µF
C29 "C0402C104K4RACTU" CAP-0402#1 91,58.5 r180 top value=100nF
C30 "C0402C104K4RACTU" CAP-0402#1 92.9,58.5 r0 top value=100nF
C31 "C0402C105K8PACTU" CAP-0402#2 31.565,66.015 r270 top value=1µF
C32 "C0402C104K4RACTU" CAP-0402#1 18.05,72.005 r180 top value=100nF
C33 "C0402C105K8PACTU" CAP-0402#2 28.9,64.465 r270 top value=1µF
C34 "C0402C103K5RACTU" CAP-0402#2 19.73,37.28 r90 top value=10nF
C35 "C0402C104K4RACTU" CAP-0402#1 24.967,64.465 r90 top value=100nF
C36 "C0402C104K4RACTU" CAP-0402#1 26,64.465 r90 top value=100nF
C37 "C0402C104K4RACTU" CAP-0402#1 27.5,64.465 r90 top value=100nF
C38 "C0402C105K8PACTU" CAP-0402#1 21.1,87.3 r90 top value=1µF
C39 "C0402C182J3GAC7867" CAP-0402#1 22.2,85.435 r270 top value=1.8nF
C40 "C0402C182J3GAC7867" CAP-0402#1 30.051,91.67 r0 top value=1.8nF
C41 "C0402C105K8PACTU" CAP-0402#1 29.622,95.162 r90 top value=1µF
C42 "C0402C105K8PACTU" CAP-0402#1 41.75,85.75 r90 top value=1µF
C43 "C0402C104K4RACTU" CAP-0402#1 20.75,71.25 r0 top value=100nF
C44 "C0402C182J3GAC7867" CAP-0402#1 41.75,87.75 r270 top value=1.8nF
C45 "C0402C182J3GAC7867" CAP-0402#1 53,93.75 r0 top value=1.8nF
C46 "GRM1555C1H151FA01D" CAP-0402#1 25.3,75 r90 top value=150pF
C47 "C0402C105K8PACTU" CAP-0402#1 52.5,92.25 r90 top value=1µF
C48 "C0402C104K4RACTU" CAP-0402#1 32,70.45 r0 top value=100nF
C49 "C0402C105K8PACTU" CAP-0402#1 32,71.45 r0 top value=1µF
C50 "GRM1555C1H151FA01D" CAP-0402#1 24.3,75 r90 top value=150pF
C51 "C0402C104K4RACTU" CAP-0402#1 32,72.45 r180 top value=100nF
C52 "C0402C104K4RACTU" CAP-0402#2 9.339,24.123 r90 top value=100nF
C53 "C0402C104K4RACTU" CAP-0402#2 79.565,12.7 r0 top value=100nF
C54 "C0402C104K4RACTU" CAP-0402#2 75.965,12.7 r180 top value=100nF
C55 "C0402C104K4RACTU" CAP-0402#2 74.165,12.7 r180 top value=100nF
C56 "C0402C104K4RACTU" CAP-0402#2 77.765,12.7 r0 top value=100nF
C57 "C0603C105K3PACTU" CAP-0603#2 81.1,13.55 r270 top value=1µF
C58 "C0402C104K4RACTU" CAP-0402#1 77.25,29.25 r0 top value=100nF
C59 "C0402C104K4RACTU" CAP-0402#1 73.465,21.5 r0 top value=100nF
C60 "C0402C104K4RACTU" CAP-0402#1 6.984,87.138 r0 top value=100nF
C61 "CL31A107MPHNNNE" CAP-1206#2 78.15,66.01 r0 top value=100µF
C62 "CL31A107MPHNNNE" CAP-1206#2 78.15,68.31 r0 top value=100µF
C63 "C0402C104K4RACTU" CAP-0402#2 51.283,30.333 r270 top value=100nF
C64 "C3216X5R1A686M160AC" CAP-1206#2 90.3,45.6 r270 top value=68µF
C65 "C0402C100K5RACTU" CAP-0402#2 84.588,61.259 r0 top value=1nF
C66 "C0402C100K5RACTU" CAP-0402#1 43,41.835 r270 top value=1nF
C67 "C0402C104K4RACTU" CAP-0402#1 42,41.835 r270 top value=100nF
C68 "C0402C100K5RACTU" CAP-0402#1 43,30.55 r0 top value=1nF
C69 "C0402C104K4RACTU" CAP-0402#1 43,31.55 r0 top value=100nF
C70 "C0402C100K5RACTU" CAP-0402#1 48.5,36.25 r180 top value=1nF
C71 "C0402C100K5RACTU" CAP-0402#1 44.5,31.05 r90 top value=1nF
C72 "C0402C100K5RACTU" CAP-0402#1 40.139,42.273 r270 top value=1nF
C73 "C0402C100K5RACTU" CAP-0402#1 40.068,31.75 r90 top value=1nF
C74 "C0402C100K5RACTU" CAP-0402#1 41.017,31.75 r90 top value=1nF
C75 "C0402C100K5RACTU" CAP-0402#1 48.462,41.087 r180 top value=1nF
C76 "GRM188R61E106MA73J" CAP-0603#1 38.939,42.688 r270 top value=10µF
C77 "GRM188R61E106MA73J" CAP-0603#1 38.756,39.314 r0 top value=10µF
C78 "CL31A107MPHNNNE" CAP-1206#1 41.039,19.513 r270 top value=100µF
C79 "CL31A107MPHNNNE" CAP-1206#1 43.439,18.338 r270 top value=100µF
C80 "C0805C472KDRACTU" CAP-0805#1 44,10.75 r180 top value=4.7nF
C81 "C0402C104K4RACTU" CAP-0402#1 16.841,23.465 r90 top value=100nF
C82 "C0402C103K5RACTU" CAP-0402#2 18.73,37.28 r90 top value=10nF
C83 "CL21A226MAQNNNE" CAP-0805#2 15.71,41.915 r270 top value=22µF
C84 "GRM155R61H473KE14D" CAP-0402#1 93.35,44.16 r270 top value=47nF
C85 "ZRB18AR60J476ME01L" CAP-0603#1 95.65,40.95 r270 top value=47µF
C86 "GRM155R60J475ME47D" CAP-0402#1 92,44.2 r90 top value=4.7µF
C87 "C0402C105K8PACTU" CAP-0402#1 30.1,63.595 r270 top value=1µF
C88 "C0402C105K8PACTU" CAP-0402#1 28.87,59.868 r90 top value=1µF
C89 "C0402C104K4RACTU" CAP-0402#1 48.462,39.002 r180 top value=100nF
C90 "C0402C150J5GACTU" CAP-0402#1 43.833,43.532 r315 top value=15pF
C91 "C0402C150J5GACTU" CAP-0402#1 45.2,42.194 r135 top value=15pF
C92 "GRM188R61E106MA73J" CAP-0603#2 87.695,41.43 r0 top value=10µF
C93 "C0402C104K4RACTU" CAP-0402#2 20.265,44.315 r0 top value=100nF
C94 "C0402C105K8PACTU" CAP-0402#1 47.074,25.438 r180 top value=1µF
C95 "C0402C105K8PACTU" CAP-0402#1 47.074,26.318 r180 top value=1µF
C96 "C0402C105K8PACTU" CAP-0402#1 6.955,40.1 r270 top value=1µF
C97 "C0402C105K8PACTU" CAP-0402#1 10.485,44.34 r90 top value=1µF
C98 "C0402C104K4RACTU" CAP-0402#1 23.718,47.988 r180 top value=100nF
C99 "C0402C104K4RACTU" CAP-0402#1 19.07,61.575 r180 top value=100nF
C100 "C0402C104K4RACTU" CAP-0402#1 9.835,61.311 r0 top value=100nF
C101 "C0402C104K4RACTU" CAP-0402#1 7.965,48.1 r0 top value=100nF
C102 "C0402C104K4RACTU" CAP-0402#1 20.774,46.648 r180 top value=100nF
C103 "C0402C104K4RACTU" CAP-0402#1 23.389,56.203 r90 top value=100nF
C104 "ZRB18AR60J476ME01L" CAP-0603#2 28.455,40.315 r180 top value=47µF
C105 "C0402C104K4RACTU" CAP-0402#1 5.4,83.365 r90 top value=100nF
C106 "ZRB18AR60J476ME01L" CAP-0603#2 28.455,38.915 r180 top value=47µF
C107 "C0402C180J5GACTU" CAP-0402#1 24.178,49.328 r270 top value=18pF
C108 "GRM155R60J225KE95D" CAP-0402#1 7.965,49.9 r0 top value=2.2µF
C109 "C0402C104K4RACTU" CAP-0402#2 7.965,49 r0 top value=100nF
C110 "C0402C104K4RACTU" CAP-0402#2 9.785,63.093 r0 top value=100nF
C111 "GRM155R60J225KE95D" CAP-0402#1 9.835,62.227 r0 top value=2.2µF
C112 "C0402C180J5GACTU" CAP-0402#1 24.178,51.158 r90 top value=18pF
C113 "C0402C104K4RACTU" CAP-0402#1 51.283,34.469 r270 top value=100nF
C114 "C0402C104K4RACTU" CAP-0402#1 56.719,31.573 r90 top value=100nF
C115 "C0402C104K4RACTU" CAP-0402#1 56.719,34.473 r270 top value=100nF
C116 "CL21A226MAQNNNE" CAP-0805#2 82.12,87.879 r0 top value=22µF
C117 "GRM155R60J225KE95D" CAP-0402#2 6.055,40.1 r270 top value=2.2µF
C118 "CL21A226MAQNNNE" CAP-0805#2 82.12,89.761 r0 top value=22µF
C119 "CL21A226MAQNNNE" CAP-0805#2 82.12,85.997 r0 top value=22µF
C120 "CL21A226MAQNNNE" CAP-0805#2 82.12,84.115 r0 top value=22µF
C121 "CL21A226MAQNNNE" CAP-0805#2 78.82,87.879 r0 top value=22µF
C122 "CL21A226MAQNNNE" CAP-0805#2 78.82,89.761 r0 top value=22µF
C123 "CL21A226MAQNNNE" CAP-0805#2 78.82,85.997 r0 top value=22µF
C124 "CL21A226MAQNNNE" CAP-0805#2 78.82,84.115 r0 top value=22µF
C125 "ZRB18AR60J476ME01L" CAP-0603#2 28.425,41.815 r180 top value=47µF
C126 "ZRB18AR60J476ME01L" CAP-0603#2 28.425,43.215 r180 top value=47µF
C127 "C0402C103K5RACTU" CAP-0402#2 20.73,38.38 r270 top value=10nF
C128 "GRM1555C1H151FA01D" CAP-0402#2 17.195,38.815 r180 top value=150pF
C129 "CL21A226MAQNNNE" CAP-0805#2 13.83,41.915 r270 top value=22µF
C130 "ZRB18AR60J476ME01L" CAP-0603#2 22.141,24.59 r0 top value=47µF
C131 "ZRB18AR60J476ME01L" CAP-0603#2 22.141,23.19 r0 top value=47µF
C132 "ZRB18AR60J476ME01L" CAP-0603#2 24.841,23.19 r180 top value=47µF
C133 "ZRB18AR60J476ME01L" CAP-0603#2 24.841,24.59 r180 top value=47µF
C134 "C0402C104K4RACTU" CAP-0402#2 91,51.1 r180 top value=100nF
C135 "C0402C104K4RACTU" CAP-0402#2 92.9,51.1 r0 top value=100nF
C136 "C0402C104K4RACTU" CAP-0402#2 91,62.2 r180 top value=100nF
C137 "C0402C104K4RACTU" CAP-0402#2 92.9,62.2 r0 top value=100nF
C138 "C0402C104K4RACTU" CAP-0402#2 91,54.8 r180 top value=100nF
C139 "C0402C104K4RACTU" CAP-0402#2 92.9,54.8 r0 top value=100nF
C140 "ZRB18AR60J476ME01L" CAP-0603#2 97,40.95 r270 top value=47µF
C141 "CL31A107MPHNNNE" CAP-1206#2 72.375,64.835 r90 top value=100µF
C142 "CL31A107MPHNNNE" CAP-1206#2 70.075,64.835 r90 top value=100µF
C143 "CL31A107MPHNNNE" CAP-1206#2 67.775,64.835 r90 top value=100µF
C144 "CL31A107MPHNNNE" CAP-1206#2 78.15,59.11 r0 top value=100µF
C145 "CL31A107MPHNNNE" CAP-1206#2 78.15,61.41 r0 top value=100µF
C146 "CL31A107MPHNNNE" CAP-1206#2 78.15,63.71 r0 top value=100µF
C147 "GRM1555C1H151FA01D" CAP-0402#2 84.303,66.259 r0 top value=150pF
C148 "CL31A107MPHNNNE" CAP-1206#2 90.475,64.7 r180 top value=100µF
C149 "CL31A107MPHNNNE" CAP-1206#2 90.475,67 r180 top value=100µF
C150 "CL31A107MPHNNNE" CAP-1206#2 85.5,69.075 r270 top value=100µF
C151 "CL31A107MPHNNNE" CAP-1206#2 83.2,69.075 r270 top value=100µF
C152 "C0402C104K4RACTU" CAP-0402#2 16.5,43.935 r270 bottom value=100nF
C153 "CC0402JRNPO8BN470" CAP-0402#2 17.6,43.935 r270 bottom value=47pF
C154 "CC0402JRNPO8BN470" CAP-0402#2 13.6,43.935 r270 bottom value=47pF
C155 "CC0402JRNPO8BN470" CAP-0402#2 11.4,43.935 r270 bottom value=47pF
C156 "CC0402JRNPO8BN470" CAP-0402#2 9.2,43.935 r270 bottom value=47pF
C157 "C0805C472KDRACTU" CAP-0805#2 2.45,47.2 r0 top value=4.7nF
C158 "C0805C472KDRACTU" CAP-0805#2 2.45,68.4 r0 top value=4.7nF
CAN0_RX "CMP-018-0005-A.3" TP-1.00MM#1 75,27 r180 bottom
CAN0_TX "CMP-018-0005-A.3" TP-1.00MM#1 77,27 r180 bottom
CAN1_RX "CMP-018-0005-A.3" TP-1.00MM#1 73,27 r180 bottom
CAN1_TX "CMP-018-0005-A.3" TP-1.00MM#1 71,27 r180 bottom
CANH "CMP-018-0005-A.3" TP-1.00MM#1 75,11 r180 bottom
CANL "CMP-018-0005-A.3" TP-1.00MM#1 75,13 r180 bottom
CN1 "FTSH-105-01-F-DV" FTSH-105-01-F-DV-Footprint-1 3.528,21.085 r270 top
CN2 "HPH2-A-10-SGA" PINHEAD_2X05_127 4.209,92.793 r270 top
CN3 "HPH2-A-10-SGA" PINHEAD_2X05_127 2.304,86.678 r0 top
CS_AIN2A "CMP-018-0005-A.3" TP-1.00MM#1 41,98 r180 bottom
CS_AIN2B "CMP-018-0005-A.3" TP-1.00MM#1 21,90 r180 bottom
CS_AIN3A "CMP-018-0005-A.3" TP-1.00MM#1 43,96 r180 bottom
CS_AIN3B "CMP-018-0005-A.3" TP-1.00MM#1 43,98 r180 bottom
D1 "PESD0402-140CT-ND" 0402#1 53.9,85.95 r270 top
D2 "PESD0402-140CT-ND" 0402#1 55.1,85.95 r270 top
D3 "PESD0402-140CT-ND" 0402#1 52.7,85.95 r270 top
D4 "PESD0402-140CT-ND" 0402#1 70.9,89.9 r180 top
D5 "PRTR5V0U2X,215" SOT190P230X110-4N 32.3,17.75 r90 top
D6 "PRTR5V0U2X,215" SOT190P230X110-4N 36.05,17.75 r90 top
D7 "PRTR5V0U2X,215" SOT190P230X110-4N 6.75,44.74 r270 top
D8 "PRTR5V0U2X,215" SOT190P230X110-4N 6.748,60.888 r90 top
D9 "PESD0402-140CT-ND" 0402#1 51.5,85.95 r270 top
D10 "PESD5V0S1UA,115" SOD323 87.7,69.3 r270 top
D11 "BAV70M,315" SOT883 24.3,62.5 r0 top
D12 "PESD0402-140CT-ND" 0402#1 35.075,83.925 r0 top
D13 "PESD0402-140" 0402#2 18.7,43.95 r90 bottom
D14 "PESD0402-140" 0402#2 14.7,43.95 r90 bottom
D15 "PESD0402-140" 0402#2 12.5,43.95 r90 bottom
D16 "PESD0402-140" 0402#2 10.3,43.95 r90 bottom
DBG_3V3 "CMP-018-0005-A.3" TP-1.00MM#2 12,65.564 r90 bottom
DBG_BOOT "CMP-018-0005-A.3" TP-1.00MM#1 12,70.05 r90 bottom
DBG_GND "CMP-018-0005-A.3" TP-1.00MM#1 12,68.05 r90 bottom
DBG_SWCLK "CMP-018-0005-A.3" TP-1.00MM#3 9.314,70.101 r90 bottom
DBG_SWDIO "CMP-018-0005-A.3" TP-1.00MM#1 10,68.05 r90 bottom
DGB_RST "CMP-018-0005-A.3" TP-1.00MM#1 24,53 r180 bottom
EN_485 "CMP-018-0005-A.3" TP-1.00MM#1 77,17 r180 bottom
EN_CAN "CMP-018-0005-A.3" TP-1.00MM#1 79,22 r180 bottom
ETH_L1 "CMP-018-0005-A.3" TP-1.00MM#1 62,17 r180 bottom
ETH_L2 "CMP-018-0005-A.3" TP-1.00MM#1 60,17 r180 bottom
F1 "0ZCG0050AF2C" 1812 65.4,7.7 r180 top
Fiducial_1 "Fiducial mark 1mm with 2mm solder" "Fiducial mark 1mm with circle-Footprint-1" 8,98 r90 top
Fiducial_2 "Fiducial mark 1mm with 2mm solder" "Fiducial mark 1mm with circle-Footprint-1" 99,12 r90 top
Fiducial_3 "Fiducial mark 1mm with 2mm solder" "Fiducial mark 1mm with circle-Footprint-1" 82,98 r90 top
GND_3V3_1 "CMP-018-0005-A.3" TP-1.00MM#1 67,8 r90 bottom
GND_3V3_2 "CMP-018-0005-A.3" TP-1.00MM#1 67,10 r90 bottom
GND_3V8_1 "CMP-018-0005-A.3" TP-1.00MM#1 70,71 r180 bottom
GND_3V8_2 "CMP-018-0005-A.3" TP-1.00MM#1 64,71 r180 bottom
GND_3V8_3 "CMP-018-0005-A.3" TP-1.00MM#1 68,71 r180 bottom
H1 "9774070151R" 9774070151R 29.161,78.93 r180 top
H2 "9774070151R" 9774070151R 4.961,78.93 r180 top locked
H3 "9774070151R" 9774070151R 29.161,54.78 r180 top locked
H4 "9774070151R" 9774070151R 4.961,54.78 r180 top locked
H/Fn "CMP-018-0005-A.3" TP-1.00MM#1 75,17 r180 bottom
HUB_EN0 "CMP-018-0005-A.3" TP-1.00MM#1 42,25 r270 bottom
HUB_EN1 "CMP-018-0005-A.3" TP-1.00MM#1 40,25 r270 bottom
HUB_EN2 "CMP-018-0005-A.3" TP-1.00MM#1 38,25 r270 bottom
HUB_SCL "CMP-018-0005-A.3" TP-1.00MM#1 89,40 r180 bottom
HUB_SDA "CMP-018-0005-A.3" TP-1.00MM#1 89,38 r180 bottom
I2C1_SCL "CMP-018-0005-A.3" TP-1.00MM#1 32,43 r180 bottom
I2C1_SDA "CMP-018-0005-A.3" TP-1.00MM#1 32,45 r180 bottom
I2C2_SCL "CMP-018-0005-A.3" TP-1.00MM#1 21,64 r180 bottom
I2C2_SDA "CMP-018-0005-A.3" TP-1.00MM#1 21,62 r180 bottom
I2S_CK "CMP-018-0005-A.3" TP-1.00MM#1 23,71 r180 bottom
I2S_SDI "CMP-018-0005-A.3" TP-1.00MM#1 21,72 r180 bottom
I2S_SDO "CMP-018-0005-A.3" TP-1.00MM#1 21,68 r180 bottom
I2S_WS "CMP-018-0005-A.3" TP-1.00MM#1 21,70 r180 bottom
INT_BQ "CMP-018-0005-A.3" TP-1.00MM#1 93,37 r90 bottom
J1 "DF40HC(3.5)-80DS-0.4V(51)-LEFT" DF40HC(3.5)-80DS-0.4V(51)-Footprint-1 54.61,17.145 r180 top locked
J2 "DF40HC(3.5)-80DS-0.4V(51)-RIGHT" DF40HC(3.5)-80DS-0.4V(51)-Footprint-1 54.61,60.325 r0 top locked
J3 "73100-0114" MOLX-731000114_V 74.422,96.774 r270 top locked
J4 "2-1734248-0" 2-1734248-0-Footprint-1 78.75,43.75 r0 top
J5 "FW-20-05-G-D-254-150" FW-20-05-G-D-254-150-Footprint-1 71.25,43.5 r0 top locked
J6 "615006138421" 615006138421 89.8,4.5 r0 top
J7 "615004143821" 615004143821 75,4.5 r0 top locked
J8 "1759546-1" 1759546-1 17.057,31.027 r0 top locked
J9 "73100-0114" MOLX-731000114_V 13.335,97.028 r270 top locked
J10 "ZX62-AB-5PA(31)" ZX62-AB-5PA 1.6,41.31 r270 top
J11 "114-00841-68" AMPHENOL_114-00841-68 55.118,7.25 r0 top
J12 "SJ-3524-SMT-TR" SJ-3524-SMT-TR-Footprint-1 36.588,95.17 r270 top locked
J13 "SJ-3524-SMT-TR" SJ-3524-SMT-TR-Footprint-1 25.412,95.17 r270 top locked
J14 "SJ-3524-SMT-TR" SJ-3524-SMT-TR-Footprint-1 47.764,95.17 r270 top locked
J15 "61400826021" 61400826021 33.8,6.6 r0 top
J16 "254TR" 254TR-Footprint-1 92.1,14.343 r90 top locked
J17 "TRJK7003A97NL" "TRJK0071AWNL -Footprint-2" 16.05,17.8 r0 top locked
J18 "254TR" 254TR-Footprint-1 92.1,86.573 r270 top locked
J19 "ZX62-AB-5PA(31)" ZX62-AB-5PA 1.6,62.446 r270 top
J20 "110990030" HW4-2.0 36.6,75.5 r270 top
JTAG_GND "CMP-018-0005-A.3" TP-1.00MM#1 2,19 r90 bottom
JTAG_RST "CMP-018-0005-A.3" TP-1.00MM#1 2,27 r0 bottom
JTAG_SCK "CMP-018-0005-A.3" TP-1.00MM#1 2,23 r0 bottom
JTAG_SWD "CMP-018-0005-A.3" TP-1.00MM#1 2,25 r0 bottom
JTAG_SWO "CMP-018-0005-A.3" TP-1.00MM#1 2,21 r0 bottom
JTAG_TDI "CMP-018-0005-A.3" TP-1.00MM#4 2.588,29 r90 bottom
L1 "LQG15HN39NJ02D" 0402#3 72.168,85.932 r135 top
L2 "LQG15HS68NJ02D" 0402#3 73.972,92.078 r0 top
L3 "SRP4020TA-2R2M" SRP4020#1 83.375,80.21 r270 top
L4 "BLM18EG221SN1D" L-0603 39.19,40.6 r0 top
L5 "SRP4020TA-2R2M" SRP4020#1 97.1,44.7 r0 top
L6 "SRP4020TA-3R3M" SRP4020#2 23.939,41.538 r0 top value=3.3uH
LoRa_3V3 "CMP-018-0005-A.3" TP-1.00MM#5 11.041,78.711 r90 bottom (schematic designator LORA_3V3)
LoRa_GND "CMP-018-0005-A.3" TP-1.00MM#6 18.533,79.168 r90 bottom (schematic designator LORA_GND)
LORA_IRQ "CMP-018-0005-A.3" TP-1.00MM#1 59,59 r180 bottom
LORA_RST "CMP-018-0005-A.3" TP-1.00MM#1 10,90 r180 bottom
LoRa_SWCLK "CMP-018-0005-A.3" TP-1.00MM#7 17.379,81.187 r90 bottom (schematic designator LORA_SWCLK)
LoRa_SWDIO "CMP-018-0005-A.3" TP-1.00MM#8 18.395,84 r90 bottom (schematic designator LORA_SWDIO)
LORA_VDD_TCX0 "CMP-018-0005-A.3" TP-1.00MM#1 11,74 r180 bottom
MCLK_EN "CMP-018-0005-A.3" TP-1.00MM#1 14,70 r90 bottom
MDTR "CMP-018-0005-A.3" TP-1.00MM#1 53,85 r180 bottom
PB1 "PTS820J25KSMTRLFS" C&K_PTS820_NO_HOLES-1 38.039,56.438 r0 top
PB2 "PTS820J25KSMTRLFS" C&K_PTS820_NO_HOLES-1 38.039,51.1 r180 top
PCIE_CLKREQ "CMP-018-0005-A.3" TP-1.00MM#1 2,37 r90 bottom
PWR_GND1 "CMP-018-0005-A.3" TP-1.00MM#1 83,97 r90 bottom
PWR_GND2 "CMP-018-0005-A.3" TP-1.00MM#1 85,97 r90 bottom
PWR_GND3 "CMP-018-0005-A.3" TP-1.00MM#1 87,97 r90 bottom
PWR_IN "CMP-018-0005-A.3" TP-1.00MM#1 83,89 r90 bottom
PWR_IN_1 "CMP-018-0005-A.3" TP-1.00MM#1 85,89 r270 bottom
PWR_IN_2 "CMP-018-0005-A.3" TP-1.00MM#1 87,89 r270 bottom
PWR_ON "CMP-018-0005-A.3" TP-1.00MM#1 71,63 r180 bottom
Q1 "DMN5L06VAK-7" SOTFL50P158X60-6N 62.125,84.5 r0 top
Q4 "SIA817EDJ-T1-GE3" SON65P205X205X75-8N-MWSD 8.945,38.155 r270 top
Q5 "DMN5L06VAK-7" SOTFL50P158X60-6N 41.289,24.538 r0 top
Q6 "DMN5L06VAK-7" SOTFL50P158X60-6N 38.491,24.538 r0 top
Q7 "DMN5L06VAK-7" SOTFL50P158X60-6N 68.625,61.31 r90 top
R1 "CRCW04021K00FKEDC" RES-0402#1 64.075,84.45 r270 top value=1k
R2 "CRCW04021M00FKED" RES-0402#1 59.825,85 r180 top value=1M
R3 "CRCW0402100KFKEDC" RES-0402#1 70.7,61.16 r180 top value=100k
R4 "CRCW04020000Z0EDC" RES-0402#1 37.22,67.5 r270 top value=0
R5 "CRCW04020000Z0EDC" RES-0402#1 36.12,67.5 r270 top value=0
R6 "CRCW04020000Z0EDC" RES-0402#1 69.55,86.85 r45 top value=0
R7 "CRCW04020000Z0EDC" RES-0402#1 56.7,84.95 r270 top value=0
R8 "CRCW04020000Z0EDC" RES-0402#1 55.1,84.45 r0 top value=0
R9 "CRCW04020000Z0EDC" RES-0402#1 6.984,89.138 r180 top value=0
R10 "CRCW040210K0FKED" RES-0402#1 6.989,86.138 r180 top value=10k
R11 "CRCW040210K0FKED" RES-0402#1 6.989,85.138 r180 top value=10k
R12 "CRCW04020000Z0EDC" RES-0402#1 10.624,74.565 r90 top value=0
R13 "CRCW04020000Z0EDC" RES-0402#1 11.615,74.565 r270 top value=0
R14 "CRCW04021M00FKED" RES-0402#1 6.984,88.138 r180 top value=1M
R15 "CRCW04020000Z0EDC" RES-0402#1 15.88,91.67 r135 top value=0
R16 "CRCW04020000Z0EDC" RES-0402#1 18.291,74.59 r270 top value=0
R17 "CRCW0402100KFKEDC" RES-0402#1 70.7,62.16 r180 top value=100k
R18 "CRCW04021M00FKED" RES-0402#1 6.989,84.138 r180 top value=1M
R19 "CRCW04020000Z0EDC" RES-0402#1 8.558,74.565 r270 top value=0
R20 "CRCW04020000Z0EDC" RES-0402#1 40.1,84.7 r180 top value=0
R21 "CRCW04020000Z0EDC" RES-0402#1 15.939,46.213 r270 top value=0
R22 "CRCW040247K5FKED" RES-0402#1 34,85.5 r180 top value=47.5k
R23 "CRCW040222R1FKED" RES-0402#1 31.384,84.5 r0 top value=22.1
R24 "CRCW0402100KFKEDC" RES-0402#1 30,100 r180 top value=100k
R25 "CRCW0402100KFKEDC" RES-0402#1 21.1,93.2 r270 top value=100k
R26 "CRCW040251R1FKED" RES-0402#1 41,93.162 r90 top value=51.1
R27 "CRCW040251R1FKED" RES-0402#1 31.5,85.75 r90 top value=51.1
R28 "CRCW0402100KFKEDC" RES-0402#1 52.75,100 r180 top value=100k
R29 "CRCW0402100KFKEDC" RES-0402#1 41.75,89.75 r90 top value=100k
R30 "CRCW04020000Z0EDC" RES-0402#2 38.95,35.05 r0 top value=0
R31 "CRCW04020000Z0EDC" RES-0402#2 38.95,36.01 r0 top value=0
R32 "CRCW0402100RJNED" RES-0402#1 21.1,85.45 r90 top value=100
R33 "CRCW0402100RJNED" RES-0402#1 29.622,93.162 r90 top value=100
R34 "CRCW04022K00JNED" RES-0402#1 20.216,66.89 r0 top value=2k
R35 "CRCW04022K00JNED" RES-0402#1 20.216,67.79 r0 top value=2k
R36 "CRCW04023K00JNED" RES-0402#1 43.75,87.75 r90 top value=3k
R37 "CRCW0402100RJNED" RES-0402#1 42.75,87.75 r90 top value=100
R38 "CRCW0402100RJNED" RES-0402#1 52.5,95.25 r90 top value=100
R39 "CRCW04023K00JNED" RES-0402#1 53.5,95.25 r90 top value=3k
R40 "CRCW04020000Z0EDC" RES-0402#1 16.819,46.213 r270 top value=0
R41 "CRCW0402100KFKEDC" RES-0402#2 45.734,25.898 r90 top value=100k
R42 "CRCW0402100KFKEDC" RES-0402#2 44.394,26.358 r0 top value=100k
R43 "CRCW04021M00FKED" RES-0402#2 72.305,13.8 r0 top value=1M
R44 "CRCW04020000Z0EDC" RES-0402#2 72.315,12.71 r180 top value=0
R45 "CRCW04021M00FKED" RES-0402#2 81.075,21.5 r0 top value=1M
R46 "CRCW04021M00FKED" RES-0402#2 78.175,20.5 r0 top value=1M
R47 "CRCW04021M00FKED" RES-0402#2 81.075,20.5 r0 top value=1M
R48 "CRCW04021M00FKED" RES-0402#2 76.325,20.5 r180 top value=1M
R49 "CRCW04021M00FKED" RES-0402#1 81.075,22.5 r0 top value=1M
R50 "CRCW040214K3FKED" RES-0402#1 67.29,71.046 r0 top value=14.3k
R51 "CRCW04020000Z0EDC" RES-0402#2 81.075,19.5 r180 top value=0
R52 "CRCW04021M00FKED" RES-0402#2 81.075,18.6 r180 top value=1M
R53 "CRCW040210K0FKED" RES-0402#1 48.5,38 r0 top value=10k
R54 "CRCW040210K0FKED" RES-0402#1 48.501,40.047 r0 top value=10k
R55 "RR0510P-123-D" RES-0402#1 41.12,41.835 r90 top value=12k
R56 "CRCW040210K0FKED" RES-0402#1 38.141,22.938 r180 top value=10k
R57 "CRCW0402100KFKEDC" RES-0402#1 25.995,62.025 r90 top value=100k
R58 "CRCW040253K6FKED" RES-0402#1 44.039,22.113 r90 top value=53.6k
R59 "CRCW04021M00FKED" RES-0402#2 44,12.75 r180 top value=1M
R60 "CRCW04020000Z0EDC" RES-0402#1 16.66,67.805 r0 top value=0
R61 "CRCW04020000Z0EDC" RES-0402#1 18.46,67.805 r180 top value=0
R62 "CRCW04020000Z0EDC" RES-0402#1 14.785,70.13 r270 top value=0
R63 "CRCW04020000Z0EDC" RES-0402#2 6.13,38.265 r180 top value=0
R64 "CRCW040249R9FKEDHP" RES-0402#2 15.755,38.34 r270 top value=49.9
R65 "RC0402FR-0734KL" RES-0402#2 19.25,38.815 r0 top value=34k
R66 "CRCW040275K0FKED" RES-0402#2 17.555,44.315 r0 top value=75k
R67 "RC0402FR-073K3L" RES-0402#2 17.195,36.915 r0 top value=3.3k
R68 "CRCW040210K0FKED" RES-0402#2 17.195,37.915 r180 top value=10k
R69 "CRCW04020000Z0EDC" RES-0402#2 22.205,38.615 r180 top value=0
R70 "CRCW040210K0FKED" RES-0402#1 90.584,36.1 r90 top value=10k
R71 "CRCW040210K0FKED" RES-0402#1 87.97,39.93 r180 top value=10k
R72 "CRCW0402100RFKED" RES-0402#1 92.616,36.1 r270 top value=100
R73 "CRCW04025K49FKED" RES-0402#1 94.509,36.103 r270 top value=5.49k
R74 "CRCW040210K0FKED" RES-0402#1 91.6,36.1 r90 top value=10k
R75 "CRCW040210K0FKED" RES-0402#1 93.632,36.1 r90 top value=10k
R76 "CRCW040210K0FKED" RES-0402#1 89.568,36.1 r90 top value=10k
R77 "CRCW0402100KFKEDC" RES-0402#1 74.591,83.49 r180 top value=100k
R78 "CRCW04021M00FKED" RES-0402#2 73.425,20.5 r0 top value=1M
R79 "CRCW04021K00FKEDC" RES-0402#1 15.71,61.575 r180 top value=1k
R80 "CRCW04020000Z0EDC" RES-0402#1 14.194,46.213 r270 top value=0
R81 "CRCW040210K0FKED" RES-0402#1 5.4,85.3 r90 top value=10k
R82 "CRCW04021K00FKEDC" RES-0402#1 19.459,46.213 r270 top value=1k
R83 "CRCW04020000Z0EDC" RES-0402#1 23.389,53.813 r90 top value=0
R84 "CRCW04021M00FKED" RES-0402#2 2.825,48.7 r0 top value=1M
R85 "CRCW04021M00FKED" RES-0402#1 2.825,69.8 r0 top value=1M
R86 "CRCW04020000Z0EDC" RES-0402#1 9.591,74.565 r270 top value=0
R87 "RC0402FR-075K1L" RES-0402#3 22.205,37.745 r0 top value=5.1k
R88 "RC0402FR-0734KL" RES-0402#2 82.153,61.734 r270 top value=34k
R89 "CRCW040210K0FKED" RES-0402#1 11.085,37.98 r90 top value=10k
R90 "CRCW04020000Z0EDC" RES-0402#1 17.699,46.213 r270 top value=0
R91 "CRCW04020000Z0EDC" RES-0402#1 18.579,46.213 r270 top value=0
R92 "CRCW08050000Z0EB" RES-0805 66.422,17.774 r90 top value=0
R93 "CRCW04020000Z0EDC" RES-0402#1 17.891,23.465 r90 top value=0
R94 "CRCW04020000Z0EDC" RES-0402#1 18.891,23.465 r90 top value=0
R95 "CRCW0402470RJNED" RES-0402#1 5.149,2.781 r270 top value=470
R96 "CRCW0402470RJNED" RES-0402#1 43.908,4.6 r0 top value=470
R97 "RC0402FR-0722RL" RES-0402#2 4.91,48.48 r90 top value=22
R98 "RC0402FR-0722RL" RES-0402#2 5.79,48.48 r90 top value=22
R99 "CRCW04020000Z0EDC" RES-0402#2 34.59,33.326 r90 top value=0
R100 "RC0402FR-0722RL" RES-0402#2 8.049,58.471 r135 top value=22
R101 "RC0402FR-0722RL" RES-0402#2 7.457,57.823 r135 top value=22
R102 "CRCW04020000Z0EDC" RES-0402#2 33.63,33.326 r90 top value=0
R103 "CRCW04020000Z0EDC" RES-0402#2 36.527,33.326 r90 top value=0
R104 "CRCW04020000Z0EDC" RES-0402#4 35.568,33.326 r90 top value=0
R105 "CRCW04020000Z0EDC" RES-0402#2 19.07,64.275 r0 top value=0
R106 "CRCW04020000Z0EDC" RES-0402#2 19.07,65.175 r0 top value=0
R107 "CRCW04020000Z0EDC" RES-0402#2 38.756,32.438 r90 top value=0
R108 "CRCW04020000Z0EDC" RES-0402#2 37.802,32.446 r90 top value=0
R109 "CRCW04020000Z0EDC" RES-0402#2 19.07,62.475 r180 top value=0
R110 "CRCW04020000Z0EDC" RES-0402#2 19.07,63.375 r180 top value=0
R111 "CRCW0402100KFKEDC" RES-0402#2 74.566,84.49 r180 top value=100k
R112 "CRCW0402100KFKEDC" RES-0402#2 39.941,22.938 r180 top value=100k
R113 "CRCW04020000Z0EDC" RES-0402#2 38.141,26.238 r0 top value=0
R114 "CRCW04020000Z0EDC" RES-0402#2 42.594,26.358 r0 top value=0
R115 "CRCW04020000Z0EDC" RES-0402#2 43.664,24.038 r0 top value=0
R116 "CRCW040210K0FKED" RES-0402#2 62.839,5.018 r0 top value=10k
R117 "CRCW040210K0FKED" RES-0402#2 62.839,4.138 r0 top value=10k
R118 "CRCW04021M00FKED" RES-0402#2 73.425,19.5 r0 top value=1M
R119 "CRCW04020000Z0EDC" RES-0402#2 2.053,15.945 r180 top value=0
R120 "CRCW040214K3FKED" RES-0402#2 81.663,58.159 r0 top value=14.3k
R121 "CRCW04025K49FKED" RES-0402#2 81.663,57.259 r180 top value=5.49k
R122 "CRCW040210K0FKED" RES-0402#2 83.153,61.734 r90 top value=10k
R123 "CRCW040214K3FKED" RES-0402#2 81.375,64.5 r0 top value=14.3k
R124 "CRCW04025K49FKED" RES-0402#2 81.375,63.58 r180 top value=5.49k
R125 "CRCW040247K5FKED" RES-0402#2 9.835,60.345 r180 top value=47.5k
R126 "CRCW040275K0FKED" RES-0402#2 9.835,59.438 r0 top value=75k
RST "CMP-018-0005-A.3" TP-1.00MM#1 68,63 r180 bottom
SDC_CD "CMP-018-0005-A.3" TP-1.00MM#1 59,5 r180 bottom
SDC_CLK "CMP-018-0005-A.3" TP-1.00MM#1 55,7 r180 bottom
SDC_CMD "CMP-018-0005-A.3" TP-1.00MM#1 53,5 r180 bottom
SDC_D0 "CMP-018-0005-A.3" TP-1.00MM#1 53,7 r270 bottom
SDC_D1 "CMP-018-0005-A.3" TP-1.00MM#1 51,7 r270 bottom
SDC_D2 "CMP-018-0005-A.3" TP-1.00MM#1 55,5 r180 bottom
SDC_D3 "CMP-018-0005-A.3" TP-1.00MM#1 57,5 r180 bottom
SERIAL0_CTS "CMP-018-0005-A.3" TP-1.00MM#1 70,19 r180 bottom
SERIAL0_RTS "CMP-018-0005-A.3" TP-1.00MM#1 70,21 r180 bottom
SERIAL0_RX "CMP-018-0005-A.3" TP-1.00MM#1 67,24 r180 bottom
SERIAL0_TX "CMP-018-0005-A.3" TP-1.00MM#1 70,17 r180 bottom
SERIAL1_CTS "CMP-018-0005-A.3" TP-1.00MM#1 89,52 r0 bottom
SERIAL1_RTS "CMP-018-0005-A.3" TP-1.00MM#1 89,54 r0 bottom
SERIAL1_RX "CMP-018-0005-A.3" TP-1.00MM#1 89,56 r0 bottom
SERIAL1_TX "CMP-018-0005-A.3" TP-1.00MM#1 89,58 r0 bottom
SERIAL2_RX "CMP-018-0005-A.3" TP-1.00MM#1 41,59 r180 bottom
SERIAL2_TX "CMP-018-0005-A.3" TP-1.00MM#1 41,57 r180 bottom
SERIAL3_RX "CMP-018-0005-A.3" TP-1.00MM#1 21,86 r90 bottom
SERIAL3_TX "CMP-018-0005-A.3" TP-1.00MM#1 21,88 r90 bottom
SIM1 "SIM8060-6-1-14-00-A" SIM8060-6-0-14-00-A-Footprint-1 62.645,93.52 r180 top
SIM2 "SIM8060-6-1-14-00-A" SIM8060-6-0-14-00-A-Footprint-1 12.74,34.645 r180 bottom locked
SIM_DET "CMP-018-0005-A.3" TP-1.00MM#1 65,86 r90 bottom
SIM_IO "CMP-018-0005-A.3" TP-1.00MM#1 65,90 r180 bottom
SIM_SCLK "CMP-018-0005-A.3" TP-1.00MM#1 63,90 r180 bottom
SIM_SRST "CMP-018-0005-A.3" TP-1.00MM#1 65,88 r180 bottom
SIM_SSW "CMP-018-0005-A.3" TP-1.00MM#1 67,88 r180 bottom
SIM_SVCC "CMP-018-0005-A.3" TP-1.00MM#1 53,89 r180 bottom
STM_BOOT0 "CMP-018-0005-A.3" TP-1.00MM#9 8.73,80 r90 bottom
SW1 "218-2LPSTRF" CTS-218-2LPST_V 37.339,61.338 r180 top
SW2 "218-2LPSTF" CTS-218-2LPST_V 30.875,21.79 r0 top
U1 "SARA-R412M-02B" SARA-96 52.25,75.5 r180 top locked
U2 "CS42L52-CNZ" QFN127P600-8N 26.25,69.5 r90 top
U3 "USB2514B/M2" MCHP-QFN-36_V 43.5,36.25 r0 top
U4 "SP335ECR1-L" QFN50P500X500X100_HS-33N 77.3,16.6 r180 top
U5 "TJA1049T/3J" TJA1049T_3J-Footprint-1 77.25,24.75 r270 top
U6 "MPM3550EGLE" LGA18C100P6X4_1200X1200X360 74.755,75.9 r0 top
U7 "NCP383LMUAJAATXG" PQFN50P300X300X55_HS-21L 46.339,22.838 r180 top
U8 "SN74LVC1T45DCKR" sc70-6 91.9,56.7 r0 top
U9 "DSC6111HI2B-012.0000" DFN120P120X89-4M 25,59.9 r180 top
U10 "SN74LVC1G125DCKR" SC70-5 17.385,69.955 r0 top
U11 "BQ24195RGET" VQFN24 92.1,40.18 r90 top
U12 "AP7311-18WG-7" SOT25 31.039,60.638 r0 top
U13 "TPS54620RGYR" RHL0014A_V 18.78,41.465 r0 top
U14 "AP2112K-3.3TRG1" SOT25 9.535,41.405 r180 top
U15 "STM32F405RGT6" STM-LQFP64_M 15.889,54.088 r180 top locked
U16 "74LVC1G157GW,125" TSOP95P280X110-6N 53.873,34.392 r180 top
U17 "74LVC1G157GW,125" TSOP95P280X110-6N 59.309,34.395 r180 top
U18 "74LVC1G157GW,125" TSOP95P280X110-6N 59.309,30.251 r180 top
U19 "74LVC1G157GW,125" TSOP95P280X110-6N 53.873,30.255 r180 top
U20 "SN74LVC1T45DCKR" sc70-6 91.9,49.3 r0 top
U21 "SN74LVC1T45DCKR" sc70-6 91.9,60.4 r0 top
U22 "SN74LVC1T45DCKR" sc70-6 91.9,53 r0 top
U23 "CMWX1ZZABZ-078" CMWX1ZZABZ 14.25,83 r90 top
U24 "LM73100RPWR" QFN50P200X200X100-16N 84.038,59.27 r90 top
U25 "LM73100RPWR" QFN50P200X200X100-16N 84.038,64.27 r90 top
USB0_DN "CMP-018-0005-A.3" TP-1.00MM#1 8,45 r90 bottom
USB0_DP "CMP-018-0005-A.3" TP-1.00MM#1 8,43 r90 bottom
USB1_DN "CMP-018-0005-A.3" TP-1.00MM#1 4,64 r0 bottom
USB1_DP "CMP-018-0005-A.3" TP-1.00MM#1 4,62 r0 bottom
USB_FS_DN "CMP-018-0005-A.3" TP-1.00MM#1 57,21 r180 bottom
USB_FS_DP "CMP-018-0005-A.3" TP-1.00MM#1 59,21 r180 bottom
USB_FS_ID "CMP-018-0005-A.3" TP-1.00MM#1 55,21 r180 bottom
USB_FS_VBUS "CMP-018-0005-A.3" TP-1.00MM#1 61,21 r180 bottom
USB_H0_DN "CMP-018-0005-A.3" TP-1.00MM#1 31,29 r270 bottom
USB_H0_DP "CMP-018-0005-A.3" TP-1.00MM#1 33,29 r270 bottom
USB_H1_DN "CMP-018-0005-A.3" TP-1.00MM#1 35,29 r270 bottom
USB_H1_DP "CMP-018-0005-A.3" TP-1.00MM#1 37,29 r270 bottom
USB_H2_DN "CMP-018-0005-A.3" TP-1.00MM#1 38,66 r180 bottom
USB_H2_DP "CMP-018-0005-A.3" TP-1.00MM#1 38,64 r180 bottom
USB_H3_DN "CMP-018-0005-A.3" TP-1.00MM#1 39,29 r270 bottom
USB_H3_DP "CMP-018-0005-A.3" TP-1.00MM#1 41,29 r270 bottom
X1 "PJ-102A" CUI-PJ-102A_V 89.462,97.5 r0 top locked
Y "CMP-018-0005-A.3" TP-1.00MM#1 89,11 r270 bottom
Y1 "CX3225GB24000P0HPQCC" CRYSTAL3.2X2.5 46.141,44.334 r135 top
Y3 "CM315D32768DZFT" ABS07 25.835,50.294 r270 top
Z "CMP-018-0005-A.3" TP-1.00MM#1 87,11 r270 bottom

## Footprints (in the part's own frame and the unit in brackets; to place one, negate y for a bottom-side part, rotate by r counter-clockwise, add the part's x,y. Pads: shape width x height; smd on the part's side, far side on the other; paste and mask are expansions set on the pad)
2-1734248-0-Footprint-1 [mm]
  rect 1.85x0.6 smd: 1(-1.9,9.5) 2(-1.9,8.5) 3(-1.9,7.5) 4(-1.9,6.5) 5(-1.9,5.5) 6(-1.9,4.5) 7(-1.9,3.5) 8(-1.9,2.5) 9(-1.9,1.5) 10(-1.9,0.5) 11(-1.9,-0.5) 12(-1.9,-1.5) 13(-1.9,-2.5) 14(-1.9,-3.5) 15(-1.9,-4.5) 16(-1.9,-5.5) 17(-1.9,-6.5) 18(-1.9,-7.5) 19(-1.9,-8.5) 20(-1.9,-9.5) 21(1.825,-9.5) 22(1.825,-8.5) 23(1.825,-7.5) 24(1.825,-6.5) 25(1.825,-5.5) 26(1.825,-4.5) 27(1.825,-3.5) 28(1.825,-2.5) 29(1.825,-1.5) 30(1.825,-0.5) 31(1.825,0.5) 32(1.825,1.5) 33(1.825,2.5) 34(1.825,3.5) 35(1.825,4.5) 36(1.825,5.5) 37(1.825,6.5) 38(1.825,7.5) 39(1.825,8.5) 40(1.825,9.5)
  silkscreen extent -2.21,10.36 -2.11,10.46, body extent -2.4,-13.7 2.45,13.7, height 5.63
254TR-Footprint-1 [mm]
  rect 4.24x3.3 hole 1.85: 1(0,0)
  rect 4.24x3.3 smd far side: 1(0,0)
  rect 4.24x5.2 hole 1.85: 2(16,0)
  rect 4.24x5.2 smd far side: 2(16,0)
  body extent 0.6,-9.3 14.4,9.3, height 19.8
0402#1 [mm] "Chip Resistor, 2-Leads, Body  0402 (in) 1005 (mm), IPC Medium Density"
  rect 0.62x0.62 smd mask+0.05: A(0.45,0) C(-0.45,0)
  body extent -0.5,-0.3 0.5,0.3, height 0.5
0402#2 [mm] "Chip Resistor, 2-Leads, Body  0402 (in) 1005 (mm), IPC Medium Density"
  rrect50% 0.62x0.62 smd mask+0.05: A(0.45,0) C(-0.45,0)
  body extent -0.5,-0.3 0.5,0.3, height 0.5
